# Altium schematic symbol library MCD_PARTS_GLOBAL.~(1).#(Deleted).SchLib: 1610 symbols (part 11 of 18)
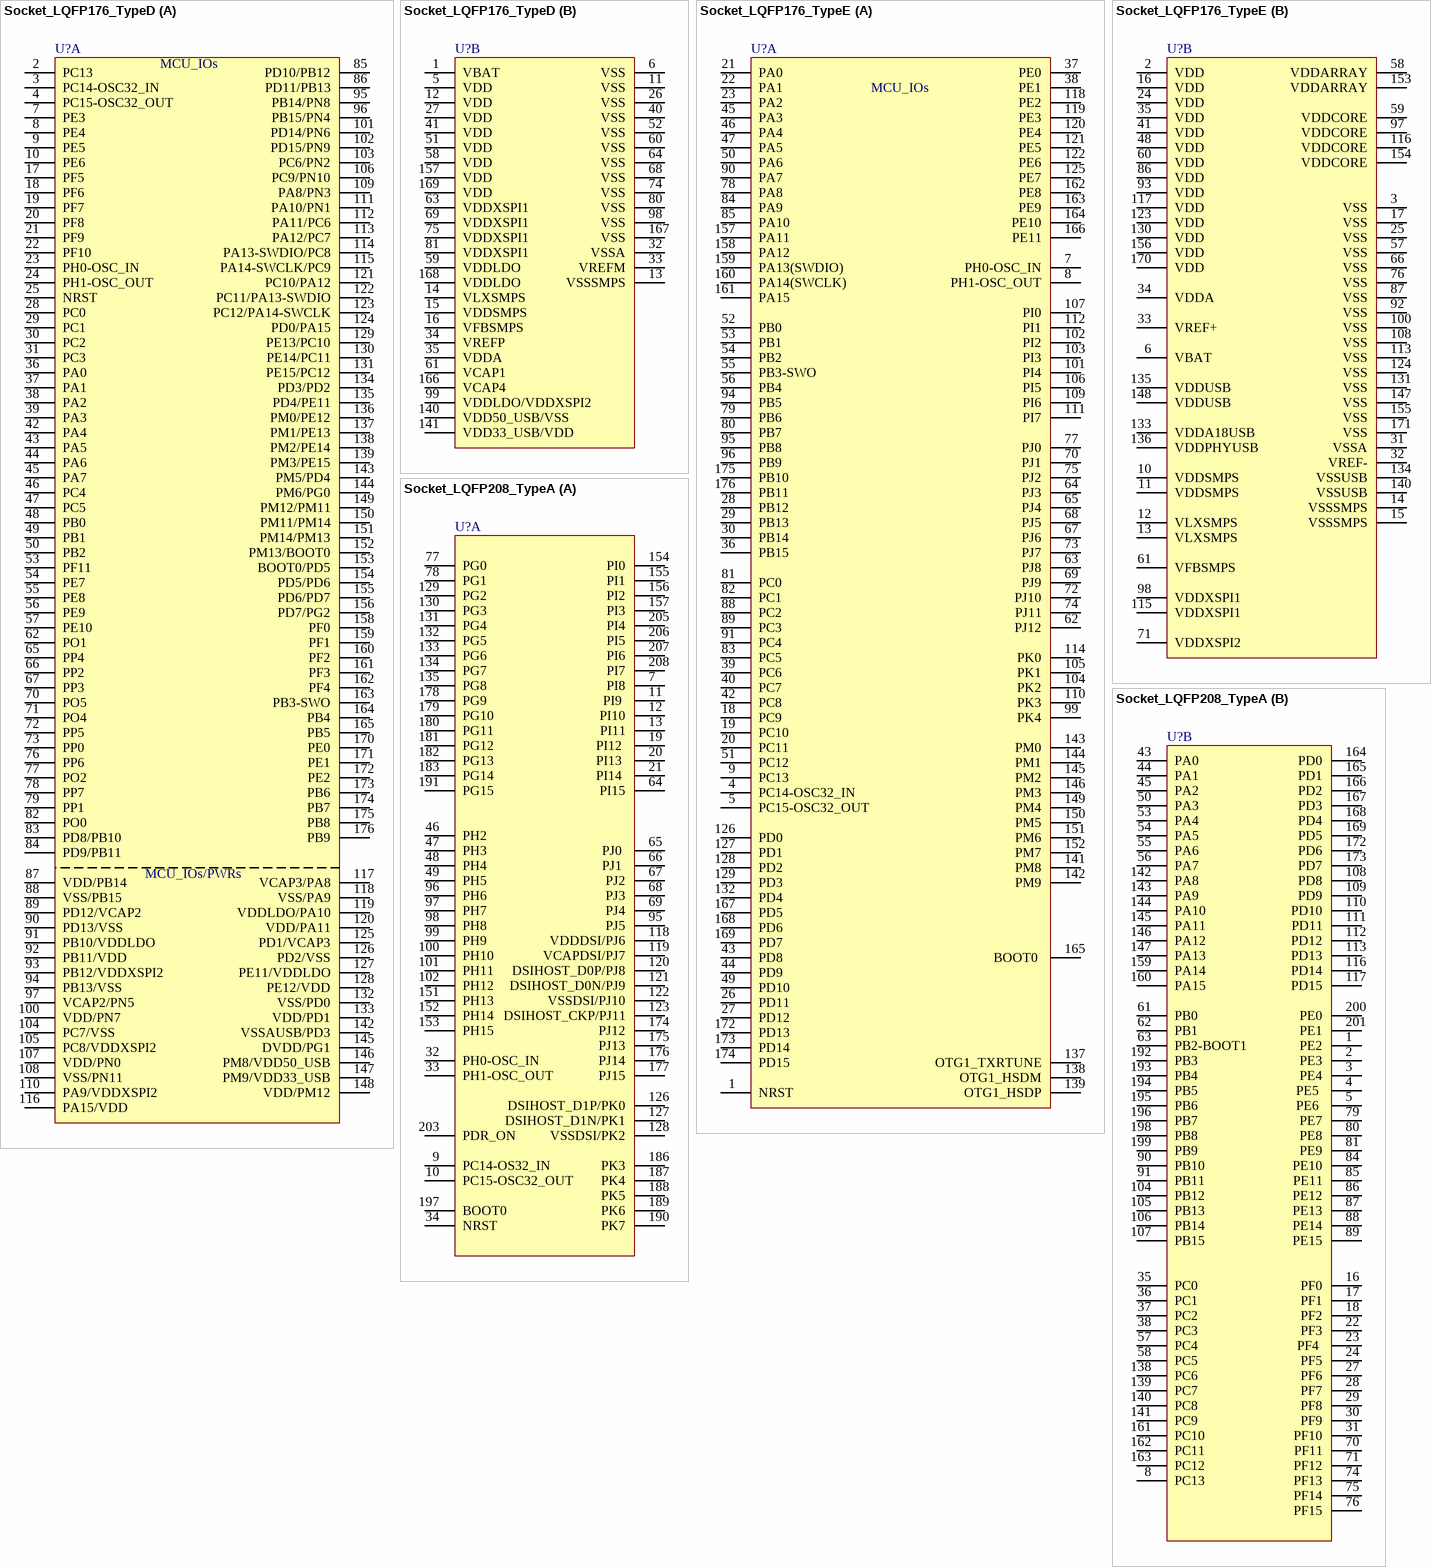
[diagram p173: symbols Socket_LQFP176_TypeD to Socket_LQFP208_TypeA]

## Socket_LQFP176_TypeD
designator U?
part A pins: 2 PC13, 3 PC14-OSC32_IN, 4 PC15-OSC32_OUT, 7 PE3, 8 PE4, 9 PE5, 10 PE6, 17 PF5, 18 PF6, 19 PF7, 20 PF8, 21 PF9, 22 PF10, 23 PH0-OSC_IN, 24 PH1-OSC_OUT, 25 NRST, 28 PC0, 29 PC1, 30 PC2, 31 PC3, 36 PA0, 37 PA1, 38 PA2, 39 PA3, 42 PA4, 43 PA5, 44 PA6, 45 PA7, 46 PC4, 47 PC5, 48 PB0, 49 PB1, 50 PB2, 53 PF11, 54 PE7, 55 PE8, 56 PE9, 57 PE10, 62 PO1, 65 PP4, 66 PP2, 67 PP3, 70 PO5, 71 PO4, 72 PP5, 73 PP0, 76 PP6, 77 PO2, 78 PP7, 79 PP1, 82 PO0, 83 PD8/PB10, 84 PD9/PB11, 85 PD10/PB12, 86 PD11/PB13, 87 VDD/PB14, 88 VSS/PB15, 89 PD12/VCAP2, 90 PD13/VSS, 91 PB10/VDDLDO, 92 PB11/VDD, 93 PB12/VDDXSPI2, 94 PB13/VSS, 95 PB14/PN8, 96 PB15/PN4, 97 VCAP2/PN5, 100 VDD/PN7, 101 PD14/PN6, 102 PD15/PN9, 103 PC6/PN2, 104 PC7/VSS, 105 PC8/VDDXSPI2, 106 PC9/PN10, 107 VDD/PN0, 108 VSS/PN11, 109 PA8/PN3, 110 PA9/VDDXSPI2, 111 PA10/PN1, 112 PA11/PC6, 113 PA12/PC7, 114 PA13-SWDIO/PC8, 115 PA14-SWCLK/PC9, 116 PA15/VDD, 117 VCAP3/PA8, 118 VSS/PA9, 119 VDDLDO/PA10, 120 VDD/PA11, 121 PC10/PA12, 122 PC11/PA13-SWDIO, 123 PC12/PA14-SWCLK, 124 PD0/PA15, 125 PD1/VCAP3, 126 PD2/VSS, 127 PE11/VDDLDO, 128 PE12/VDD, 129 PE13/PC10, 130 PE14/PC11, 131 PE15/PC12, 132 VSS/PD0, 133 VDD/PD1, 134 PD3/PD2, 135 PD4/PE11, 136 PM0/PE12, 137 PM1/PE13, 138 PM2/PE14, 139 PM3/PE15, 142 VSSAUSB/PD3, 143 PM5/PD4, 144 PM6/PG0, 145 DVDD/PG1, 146 PM8/VDD50_USB, 147 PM9/VDD33_USB, 148 VDD/PM12, 149 PM12/PM11, 150 PM11/PM14, 151 PM14/PM13, 152 PM13/BOOT0, 153 BOOT0/PD5, 154 PD5/PD6, 155 PD6/PD7, 156 PD7/PG2, 158 PF0, 159 PF1, 160 PF2, 161 PF3, 162 PF4, 163 PB3-SWO, 164 PB4, 165 PB5, 170 PE0, 171 PE1, 172 PE2, 173 PB6, 174 PB7, 175 PB8, 176 PB9
part B pins: 1 VBAT, 5 VDD, 6 VSS, 11 VSS, 12 VDD, 13 VSSSMPS, 14 VLXSMPS, 15 VDDSMPS, 16 VFBSMPS, 26 VSS, 27 VDD, 32 VSSA, 33 VREFM, 34 VREFP, 35 VDDA, 40 VSS, 41 VDD, 51 VDD, 52 VSS, 58 VDD, 59 VDDLDO, 60 VSS, 61 VCAP1, 63 VDDXSPI1, 64 VSS, 68 VSS, 69 VDDXSPI1, 74 VSS, 75 VDDXSPI1, 80 VSS, 81 VDDXSPI1, 98 VSS, 99 VDDLDO/VDDXSPI2, 140 VDD50_USB/VSS, 141 VDD33_USB/VDD, 157 VDD, 166 VCAP4, 167 VSS, 168 VDDLDO, 169 VDD

## Socket_LQFP176_TypeE
designator U?
part A pins: 1 NRST, 4 PC14-OSC32_IN, 5 PC15-OSC32_OUT, 7 PH0-OSC_IN, 8 PH1-OSC_OUT, 9 PC13, 18 PC9, 19 PC10, 20 PC11, 21 PA0, 22 PA1, 23 PA2, 26 PD11, 27 PD12, 28 PB12, 29 PB13, 30 PB14, 36 PB15, 37 PE0, 38 PE1, 39 PC6, 40 PC7, 42 PC8, 43 PD8, 44 PD9, 45 PA3, 46 PA4, 47 PA5, 49 PD10, 50 PA6, 51 PC12, 52 PB0, 53 PB1, 54 PB2, 55 PB3-SWO, 56 PB4, 62 PJ12, 63 PJ8, 64 PJ3, 65 PJ4, 67 PJ6, 68 PJ5, 69 PJ9, 70 PJ1, 72 PJ10, 73 PJ7, 74 PJ11, 75 PJ2, 77 PJ0, 78 PA8, 79 PB6, 80 PB7, 81 PC0, 82 PC1, 83 PC5, 84 PA9, 85 PA10, 88 PC2, 89 PC3, 90 PA7, 91 PC4, 94 PB5, 95 PB8, 96 PB9, 99 PK4, 101 PI4, 102 PI2, 103 PI3, 104 PK2, 105 PK1, 106 PI5, 107 PI0, 109 PI6, 110 PK3, 111 PI7, 112 PI1, 114 PK0, 118 PE2, 119 PE3, 120 PE4, 121 PE5, 122 PE6, 125 PE7, 126 PD0, 127 PD1, 128 PD2, 129 PD3, 132 PD4, 137 OTG1_TXRTUNE, 138 OTG1_HSDM, 139 OTG1_HSDP, 141 PM8, 142 PM9, 143 PM0, 144 PM1, 145 PM2, 146 PM3, 149 PM4, 150 PM5, 151 PM6, 152 PM7, 157 PA11, 158 PA12, 159 PA13(SWDIO), 160 PA14(SWCLK), 161 PA15, 162 PE8, 163 PE9, 164 PE10, 165 BOOT0 , 166 PE11, 167 PD5, 168 PD6, 169 PD7, 172 PD13, 173 PD14, 174 PD15, 175 PB10, 176 PB11
part B pins: 2 VDD, 3 VSS, 6 VBAT, 10 VDDSMPS, 11 VDDSMPS, 12 VLXSMPS, 13 VLXSMPS, 14 VSSSMPS, 15 VSSSMPS, 16 VDD, 17 VSS, 24 VDD, 25 VSS, 31 VSSA, 32 VREF-, 33 VREF+, 34 VDDA, 35 VDD, 41 VDD, 48 VDD, 57 VSS, 58 VDDARRAY, 59 VDDCORE, 60 VDD, 61 VFBSMPS, 66 VSS, 71 VDDXSPI2, 76 VSS, 86 VDD, 87 VSS, 92 VSS, 93 VDD, 97 VDDCORE, 98 VDDXSPI1, 100 VSS, 108 VSS, 113 VSS, 115 VDDXSPI1, 116 VDDCORE, 117 VDD, 123 VDD, 124 VSS, 130 VDD, 131 VSS, 133 VDDA18USB, 134 VSSUSB, 135 VDDUSB, 136 VDDPHYUSB, 140 VSSUSB, 147 VSS, 148 VDDUSB, 153 VDDARRAY, 154 VDDCORE, 155 VSS, 156 VDD, 170 VDD, 171 VSS

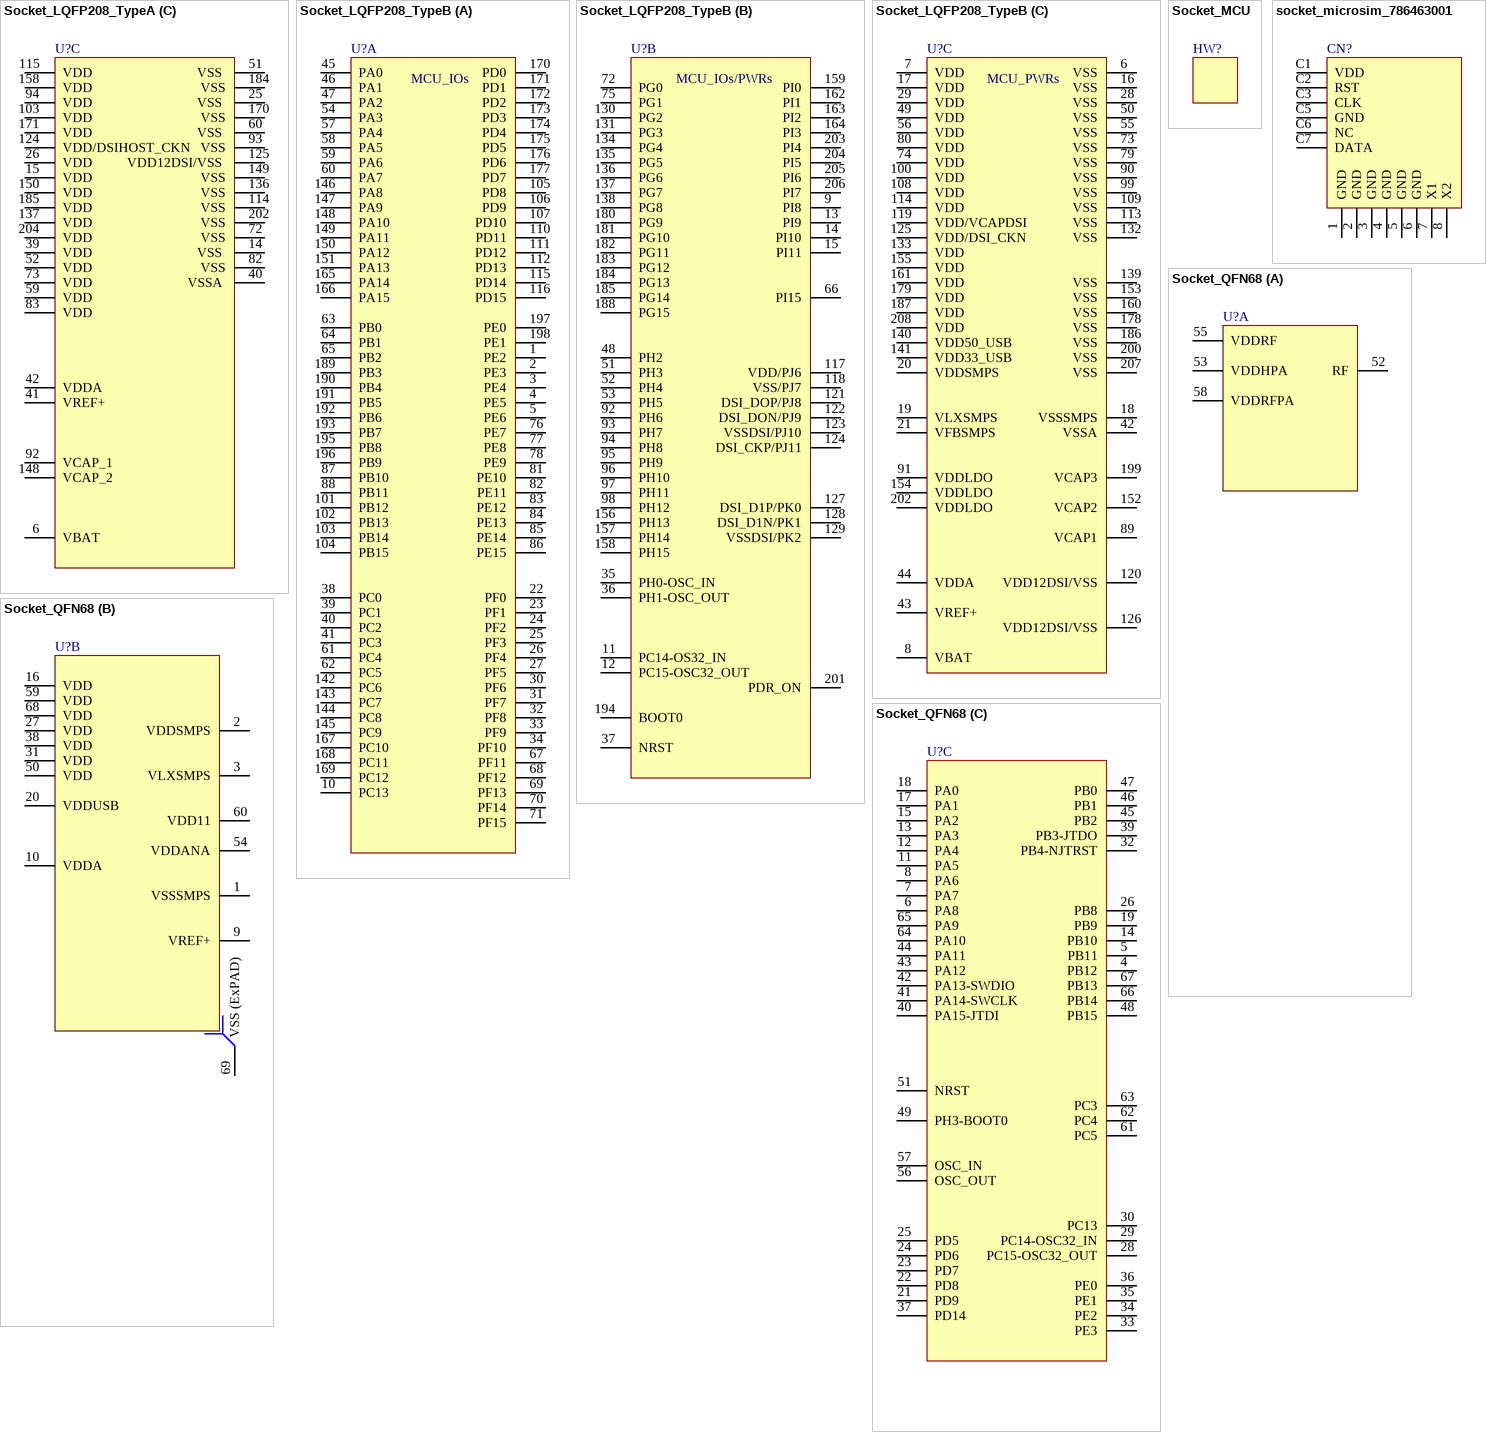
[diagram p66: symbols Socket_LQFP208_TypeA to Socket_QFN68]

## Socket_LQFP208_TypeA
designator U?
part A pins: 7 PI8, 9 PC14-OS32_IN, 10 PC15-OSC32_OUT, 11 PI9 , 12 PI10, 13 PI11, 19 PI12 , 20 PI13 , 21 PI14 , 32 PH0-OSC_IN , 33 PH1-OSC_OUT , 34 NRST , 46 PH2 , 47 PH3 , 48 PH4 , 49 PH5 , 64 PI15, 65 PJ0 , 66 PJ1 , 67 PJ2, 68 PJ3, 69 PJ4, 77 PG0, 78 PG1, 95 PJ5, 96 PH6, 97 PH7, 98 PH8, 99 PH9, 100 PH10, 101 PH11, 102 PH12, 118 VDDDSI/PJ6, 119 VCAPDSI/PJ7, 120 DSIHOST_D0P/PJ8, 121 DSIHOST_D0N/PJ9, 122 VSSDSI/PJ10, 123 DSIHOST_CKP/PJ11, 126 DSIHOST_D1P/PK0, 127 DSIHOST_D1N/PK1, 128 VSSDSI/PK2, 129 PG2, 130 PG3, 131 PG4, 132 PG5, 133 PG6, 134 PG7, 135 PG8, 151 PH13, 152 PH14, 153 PH15, 154 PI0, 155 PI1, 156 PI2, 157 PI3, 174 PJ12, 175 PJ13, 176 PJ14, 177 PJ15, 178 PG9, 179 PG10, 180 PG11, 181 PG12 , 182 PG13, 183 PG14, 186 PK3, 187 PK4, 188 PK5, 189 PK6, 190 PK7, 191 PG15, 197 BOOT0, 203 PDR_ON, 205 PI4, 206 PI5, 207 PI6, 208 PI7
part B pins: 1 PE2, 2 PE3, 3 PE4, 4 PE5 , 5 PE6 , 8 PC13 , 16 PF0, 17 PF1, 18 PF2, 22 PF3, 23 PF4 , 24 PF5, 27 PF6, 28 PF7, 29 PF8, 30 PF9, 31 PF10, 35 PC0, 36 PC1 , 37 PC2  , 38 PC3 , 43 PA0 , 44 PA1, 45 PA2 , 50 PA3 , 53 PA4 , 54 PA5 , 55 PA6, 56 PA7, 57 PC4, 58 PC5 , 61 PB0 , 62 PB1 , 63 PB2-BOOT1 , 70 PF11, 71 PF12, 74 PF13, 75 PF14, 76 PF15, 79 PE7, 80 PE8, 81 PE9, 84 PE10, 85 PE11, 86 PE12, 87 PE13, 88 PE14, 89 PE15, 90 PB10, 91 PB11, 104 PB12, 105 PB13, 106 PB14, 107 PB15, 108 PD8, 109 PD9, 110 PD10, 111 PD11, 112 PD12, 113 PD13, 116 PD14, 117 PD15, 138 PC6, 139 PC7, 140 PC8, 141 PC9, 142 PA8, 143 PA9 , 144 PA10, 145 PA11, 146 PA12, 147 PA13, 159 PA14, 160 PA15, 161 PC10, 162 PC11, 163 PC12, 164 PD0, 165 PD1, 166 PD2, 167 PD3, 168 PD4, 169 PD5, 172 PD6, 173 PD7, 192 PB3, 193 PB4, 194 PB5, 195 PB6, 196 PB7, 198 PB8, 199 PB9, 200 PE0, 201 PE1
part C pins: 6 VBAT , 14 VSS , 15 VDD, 25 VSS , 26 VDD, 39 VDD , 40 VSSA , 41 VREF+ , 42 VDDA , 51 VSS , 52 VDD, 59 VDD , 60 VSS , 72 VSS, 73 VDD, 82 VSS, 83 VDD, 92 VCAP_1, 93 VSS, 94 VDD, 103 VDD, 114 VSS, 115 VDD, 124 VDD/DSIHOST_CKN, 125 VDD12DSI/VSS , 136 VSS, 137 VDD, 148 VCAP_2 , 149 VSS, 150 VDD, 158 VDD, 170 VSS, 171 VDD, 184 VSS, 185 VDD, 202 VSS, 204 VDD

## Socket_LQFP208_TypeB
designator U?
part A pins: 1 PE2, 2 PE3, 3 PE4, 4 PE5, 5 PE6, 10 PC13, 22 PF0, 23 PF1, 24 PF2, 25 PF3, 26 PF4, 27 PF5, 30 PF6, 31 PF7, 32 PF8, 33 PF9, 34 PF10, 38 PC0, 39 PC1, 40 PC2, 41 PC3, 45 PA0, 46 PA1, 47 PA2, 54 PA3, 57 PA4, 58 PA5, 59 PA6, 60 PA7, 61 PC4, 62 PC5, 63 PB0, 64 PB1, 65 PB2, 67 PF11, 68 PF12, 69 PF13, 70 PF14, 71 PF15, 76 PE7, 77 PE8, 78 PE9, 81 PE10, 82 PE11, 83 PE12, 84 PE13, 85 PE14, 86 PE15, 87 PB10, 88 PB11, 101 PB12, 102 PB13, 103 PB14, 104 PB15, 105 PD8, 106 PD9, 107 PD10, 110 PD11, 111 PD12, 112 PD13, 115 PD14, 116 PD15, 142 PC6, 143 PC7, 144 PC8, 145 PC9, 146 PA8, 147 PA9, 148 PA10, 149 PA11, 150 PA12, 151 PA13, 165 PA14, 166 PA15, 167 PC10, 168 PC11, 169 PC12, 170 PD0, 171 PD1, 172 PD2, 173 PD3, 174 PD4, 175 PD5, 176 PD6, 177 PD7, 189 PB3, 190 PB4, 191 PB5, 192 PB6, 193 PB7, 195 PB8, 196 PB9, 197 PE0, 198 PE1
part B pins: 9 PI8, 11 PC14-OS32_IN, 12 PC15-OSC32_OUT, 13 PI9, 14 PI10, 15 PI11, 35 PH0-OSC_IN, 36 PH1-OSC_OUT, 37 NRST, 48 PH2, 51 PH3, 52 PH4, 53 PH5, 66 PI15, 72 PG0, 75 PG1, 92 PH6, 93 PH7, 94 PH8, 95 PH9, 96 PH10, 97 PH11, 98 PH12, 117 VDD/PJ6, 118 VSS/PJ7, 121 DSI_DOP/PJ8, 122 DSI_DON/PJ9, 123 VSSDSI/PJ10, 124 DSI_CKP/PJ11, 127 DSI_D1P/PK0, 128 DSI_D1N/PK1, 129 VSSDSI/PK2, 130 PG2, 131 PG3, 134 PG4, 135 PG5, 136 PG6, 137 PG7, 138 PG8, 156 PH13, 157 PH14, 158 PH15, 159 PI0, 162 PI1, 163 PI2, 164 PI3, 180 PG9, 181 PG10, 182 PG11, 183 PG12, 184 PG13, 185 PG14, 188 PG15, 194 BOOT0, 201 PDR_ON, 203 PI4, 204 PI5, 205 PI6, 206 PI7
part C pins: 6 VSS, 7 VDD, 8 VBAT, 16 VSS, 17 VDD, 18 VSSSMPS, 19 VLXSMPS, 20 VDDSMPS, 21 VFBSMPS, 28 VSS, 29 VDD, 42 VSSA, 43 VREF+, 44 VDDA, 49 VDD, 50 VSS, 55 VSS, 56 VDD, 73 VSS, 74 VDD, 79 VSS, 80 VDD, 89 VCAP1, 90 VSS, 91 VDDLDO, 99 VSS, 100 VDD, 108 VDD, 109 VSS, 113 VSS, 114 VDD, 119 VDD/VCAPDSI, 120 VDD12DSI/VSS, 125 VDD/DSI_CKN, 126 VDD12DSI/VSS, 132 VSS, 133 VDD, 139 VSS, 140 VDD50_USB, 141 VDD33_USB, 152 VCAP2, 153 VSS, 154 VDDLDO, 155 VDD, 160 VSS, 161 VDD, 178 VSS, 179 VDD, 186 VSS, 187 VDD, 199 VCAP3, 200 VSS, 202 VDDLDO, 207 VSS, 208 VDD

## Socket_MCU
designator HW?  (mechanical)
6 alternate drawings of the same symbol

## socket_microsim_786463001
designator CN?
pins: 1 GND, 2 GND, 3 GND, 4 GND, 5 GND, 6 GND, 7 X1, 8 X2, C1 VDD, C2 RST, C3 CLK, C5 GND, C6 NC, C7 DATA

## Socket_QFN68
designator U?
part A pins: 52 RF, 53 VDDHPA, 55 VDDRF, 58 VDDRFPA
part B pins: 1 VSSSMPS, 2 VDDSMPS, 3 VLXSMPS, 9 VREF+, 10 VDDA, 16 VDD, 20 VDDUSB, 27 VDD, 31 VDD, 38 VDD, 50 VDD, 54 VDDANA, 59 VDD, 60 VDD11, 68 VDD, 69 VSS (ExPAD)
part C pins: 4 PB12, 5 PB11, 6 PA8, 7 PA7, 8 PA6, 11 PA5, 12 PA4, 13 PA3, 14 PB10, 15 PA2, 17 PA1, 18 PA0, 19 PB9, 21 PD9, 22 PD8, 23 PD7, 24 PD6, 25 PD5, 26 PB8, 28 PC15-OSC32_OUT, 29 PC14-OSC32_IN, 30 PC13, 32 PB4-NJTRST, 33 PE3, 34 PE2, 35 PE1, 36 PE0, 37 PD14, 39 PB3-JTDO, 40 PA15-JTDI, 41 PA14-SWCLK, 42 PA13-SWDIO, 43 PA12, 44 PA11, 45 PB2, 46 PB1, 47 PB0, 48 PB15, 49 PH3-BOOT0, 51 NRST, 56 OSC_OUT, 57 OSC_IN, 61 PC5, 62 PC4, 63 PC3, 64 PA10, 65 PA9, 66 PB14, 67 PB13

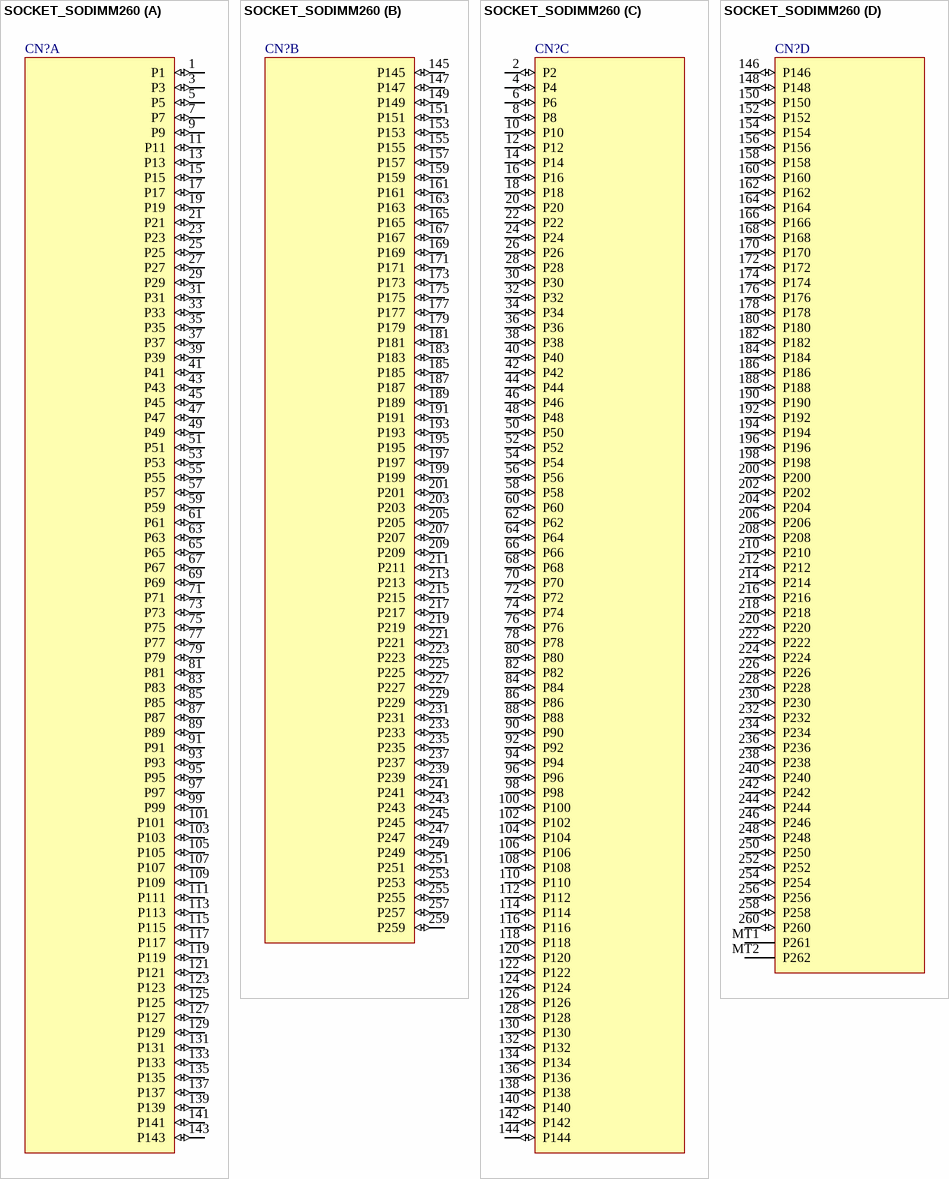
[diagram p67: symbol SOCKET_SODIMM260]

## SOCKET_SODIMM260
designator CN?
part A pins: 1 P1 (io), 3 P3 (io), 5 P5 (io), 7 P7 (io), 9 P9 (io), 11 P11 (io), 13 P13 (io), 15 P15 (io), 17 P17 (io), 19 P19 (io), 21 P21 (io), 23 P23 (io), 25 P25 (io), 27 P27 (io), 29 P29 (io), 31 P31 (io), 33 P33 (io), 35 P35 (io), 37 P37 (io), 39 P39 (io), 41 P41 (io), 43 P43 (io), 45 P45 (io), 47 P47 (io), 49 P49 (io), 51 P51 (io), 53 P53 (io), 55 P55 (io), 57 P57 (io), 59 P59 (io), 61 P61 (io), 63 P63 (io), 65 P65 (io), 67 P67 (io), 69 P69 (io), 71 P71 (io), 73 P73 (io), 75 P75 (io), 77 P77 (io), 79 P79 (io), 81 P81 (io), 83 P83 (io), 85 P85 (io), 87 P87 (io), 89 P89 (io), 91 P91 (io), 93 P93 (io), 95 P95 (io), 97 P97 (io), 99 P99 (io), 101 P101 (io), 103 P103 (io), 105 P105 (io), 107 P107 (io), 109 P109 (io), 111 P111 (io), 113 P113 (io), 115 P115 (io), 117 P117 (io), 119 P119 (io), 121 P121 (io), 123 P123 (io), 125 P125 (io), 127 P127 (io), 129 P129 (io), 131 P131 (io), 133 P133 (io), 135 P135 (io), 137 P137 (io), 139 P139 (io), 141 P141 (io), 143 P143 (io)
part B pins: 145 P145 (io), 147 P147 (io), 149 P149 (io), 151 P151 (io), 153 P153 (io), 155 P155 (io), 157 P157 (io), 159 P159 (io), 161 P161 (io), 163 P163 (io), 165 P165 (io), 167 P167 (io), 169 P169 (io), 171 P171 (io), 173 P173 (io), 175 P175 (io), 177 P177 (io), 179 P179 (io), 181 P181 (io), 183 P183 (io), 185 P185 (io), 187 P187 (io), 189 P189 (io), 191 P191 (io), 193 P193 (io), 195 P195 (io), 197 P197 (io), 199 P199 (io), 201 P201 (io), 203 P203 (io), 205 P205 (io), 207 P207 (io), 209 P209 (io), 211 P211 (io), 213 P213 (io), 215 P215 (io), 217 P217 (io), 219 P219 (io), 221 P221 (io), 223 P223 (io), 225 P225 (io), 227 P227 (io), 229 P229 (io), 231 P231 (io), 233 P233 (io), 235 P235 (io), 237 P237 (io), 239 P239 (io), 241 P241 (io), 243 P243 (io), 245 P245 (io), 247 P247 (io), 249 P249 (io), 251 P251 (io), 253 P253 (io), 255 P255 (io), 257 P257 (io), 259 P259 (io)
part C pins: 2 P2 (io), 4 P4 (io), 6 P6 (io), 8 P8 (io), 10 P10 (io), 12 P12 (io), 14 P14 (io), 16 P16 (io), 18 P18 (io), 20 P20 (io), 22 P22 (io), 24 P24 (io), 26 P26 (io), 28 P28 (io), 30 P30 (io), 32 P32 (io), 34 P34 (io), 36 P36 (io), 38 P38 (io), 40 P40 (io), 42 P42 (io), 44 P44 (io), 46 P46 (io), 48 P48 (io), 50 P50 (io), 52 P52 (io), 54 P54 (io), 56 P56 (io), 58 P58 (io), 60 P60 (io), 62 P62 (io), 64 P64 (io), 66 P66 (io), 68 P68 (io), 70 P70 (io), 72 P72 (io), 74 P74 (io), 76 P76 (io), 78 P78 (io), 80 P80 (io), 82 P82 (io), 84 P84 (io), 86 P86 (io), 88 P88 (io), 90 P90 (io), 92 P92 (io), 94 P94 (io), 96 P96 (io), 98 P98 (io), 100 P100 (io), 102 P102 (io), 104 P104 (io), 106 P106 (io), 108 P108 (io), 110 P110 (io), 112 P112 (io), 114 P114 (io), 116 P116 (io), 118 P118 (io), 120 P120 (io), 122 P122 (io), 124 P124 (io), 126 P126 (io), 128 P128 (io), 130 P130 (io), 132 P132 (io), 134 P134 (io), 136 P136 (io), 138 P138 (io), 140 P140 (io), 142 P142 (io), 144 P144 (io)
part D pins: 146 P146 (io), 148 P148 (io), 150 P150 (io), 152 P152 (io), 154 P154 (io), 156 P156 (io), 158 P158 (io), 160 P160 (io), 162 P162 (io), 164 P164 (io), 166 P166 (io), 168 P168 (io), 170 P170 (io), 172 P172 (io), 174 P174 (io), 176 P176 (io), 178 P178 (io), 180 P180 (io), 182 P182 (io), 184 P184 (io), 186 P186 (io), 188 P188 (io), 190 P190 (io), 192 P192 (io), 194 P194 (io), 196 P196 (io), 198 P198 (io), 200 P200 (io), 202 P202 (io), 204 P204 (io), 206 P206 (io), 208 P208 (io), 210 P210 (io), 212 P212 (io), 214 P214 (io), 216 P216 (io), 218 P218 (io), 220 P220 (io), 222 P222 (io), 224 P224 (io), 226 P226 (io), 228 P228 (io), 230 P230 (io), 232 P232 (io), 234 P234 (io), 236 P236 (io), 238 P238 (io), 240 P240 (io), 242 P242 (io), 244 P244 (io), 246 P246 (io), 248 P248 (io), 250 P250 (io), 252 P252 (io), 254 P254 (io), 256 P256 (io), 258 P258 (io), 260 P260 (io), MT1 P261, MT2 P262

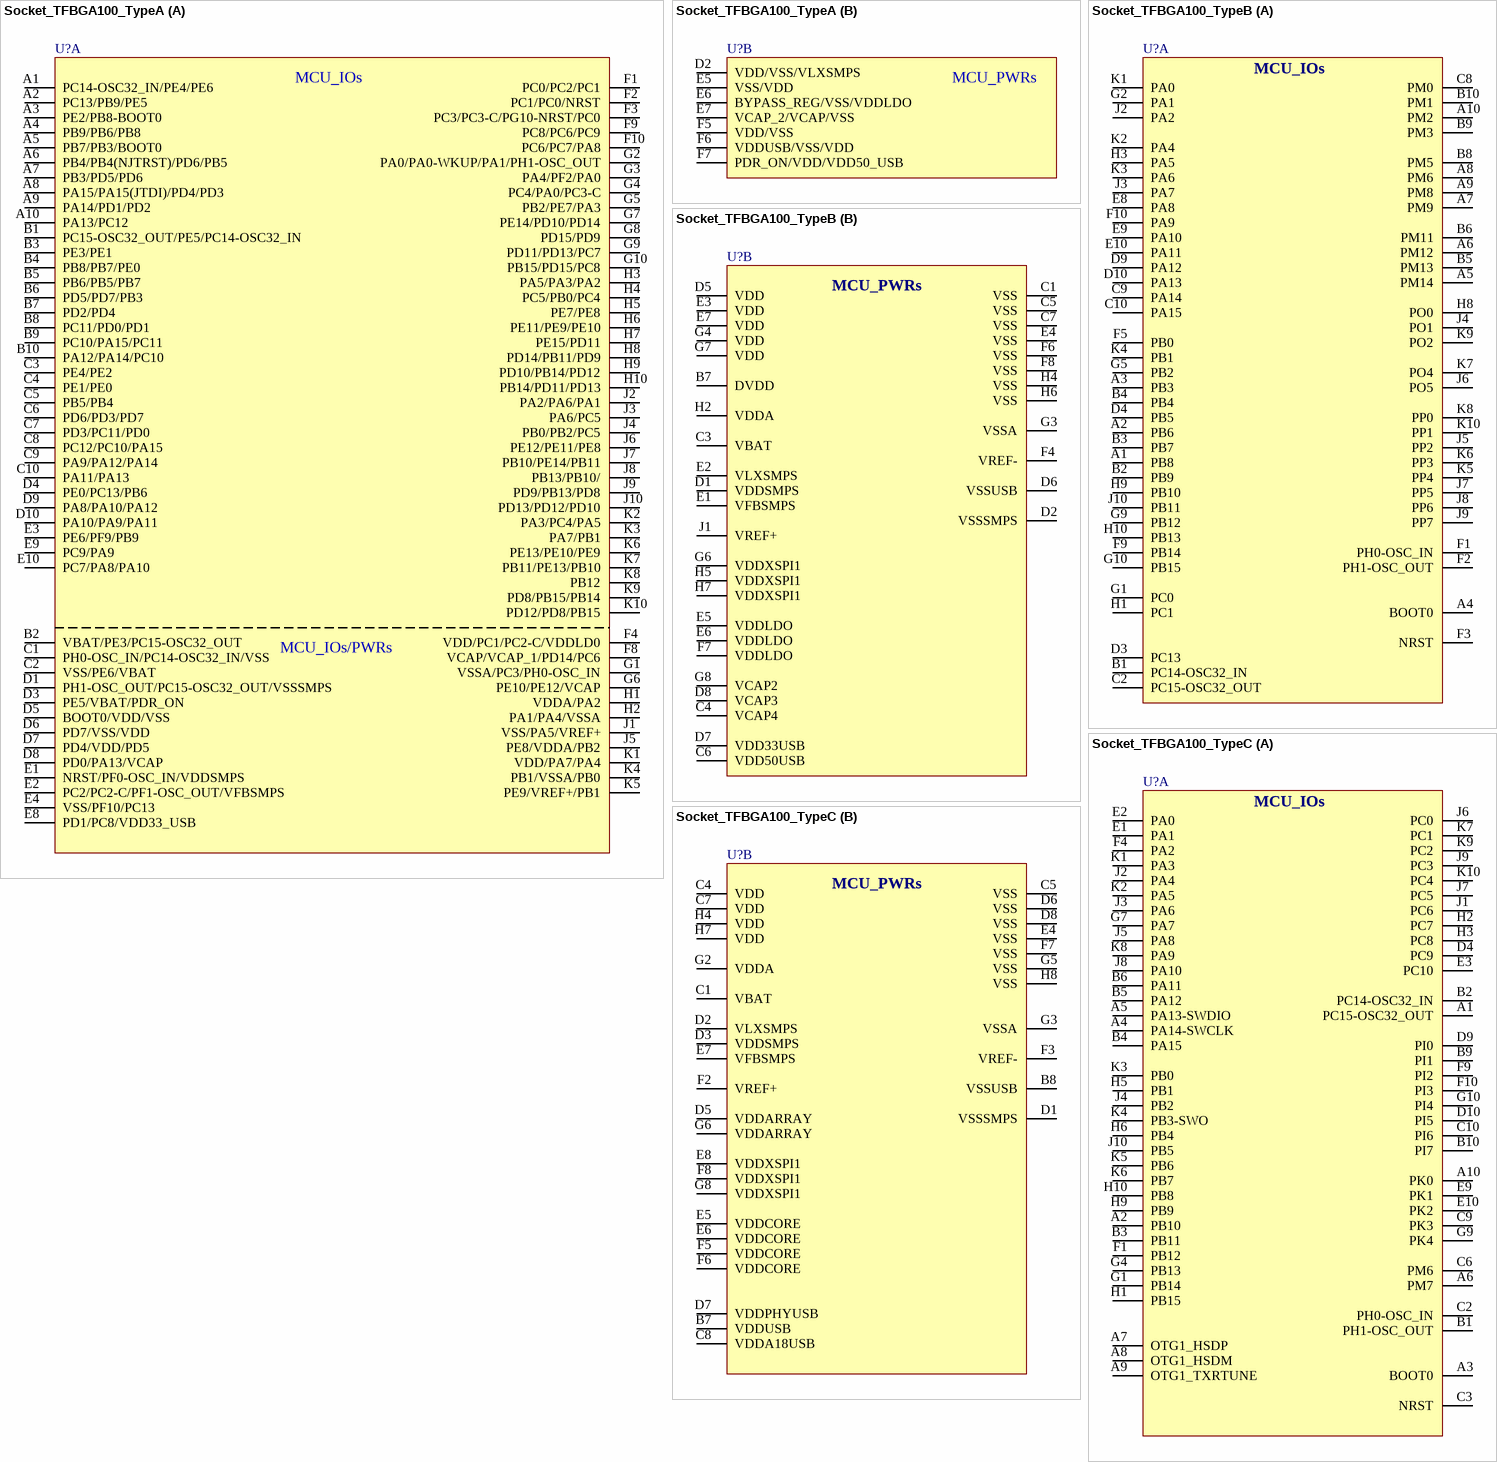
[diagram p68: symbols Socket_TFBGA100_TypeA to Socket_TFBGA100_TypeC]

## Socket_TFBGA100_TypeA
designator U?
part A pins: A1 PC14-OSC32_IN/PE4/PE6, A2 PC13/PB9/PE5, A3 PE2/PB8-BOOT0, A4 PB9/PB6/PB8, A5 PB7/PB3/BOOT0, A6 PB4/PB4(NJTRST)/PD6/PB5, A7 PB3/PD5/PD6, A8 PA15/PA15(JTDI)/PD4/PD3, A9 PA14/PD1/PD2, A10 PA13/PC12, B1 PC15-OSC32_OUT/PE5/PC14-OSC32_IN, B2 VBAT/PE3/PC15-OSC32_OUT, B3 PE3/PE1, B4 PB8/PB7/PE0, B5 PB6/PB5/PB7, B6 PD5/PD7/PB3, B7 PD2/PD4, B8 PC11/PD0/PD1, B9 PC10/PA15/PC11, B10 PA12/PA14/PC10, C1 PH0-OSC_IN/PC14-OSC32_IN/VSS, C2 VSS/PE6/VBAT, C3 PE4/PE2, C4 PE1/PE0, C5 PB5/PB4, C6 PD6/PD3/PD7, C7 PD3/PC11/PD0, C8 PC12/PC10/PA15, C9 PA9/PA12/PA14, C10 PA11/PA13, D1 PH1-OSC_OUT/PC15-OSC32_OUT/VSSSMPS, D3 PE5/VBAT/PDR_ON, D4 PE0/PC13/PB6, D5 BOOT0/VDD/VSS, D6 PD7/VSS/VDD, D7 PD4/VDD/PD5, D8 PD0/PA13/VCAP, D9 PA8/PA10/PA12, D10 PA10/PA9/PA11, E1 NRST/PF0-OSC_IN/VDDSMPS, E2 PC2/PC2-C/PF1-OSC_OUT/VFBSMPS, E3 PE6/PF9/PB9, E4 VSS/PF10/PC13, E8 PD1/PC8/VDD33_USB, E9 PC9/PA9, E10 PC7/PA8/PA10, F1 PC0/PC2/PC1, F2 PC1/PC0/NRST, F3 PC3/PC3-C/PG10-NRST/PC0, F4 VDD/PC1/PC2-C/VDDLD0, F8 VCAP/VCAP_1/PD14/PC6, F9 PC8/PC6/PC9, F10 PC6/PC7/PA8, G1 VSSA/PC3/PH0-OSC_IN, G2 PA0/PA0-WKUP/PA1/PH1-OSC_OUT, G3 PA4/PF2/PA0, G4 PC4/PA0/PC3-C, G5 PB2/PE7/PA3, G6 PE10/PE12/VCAP, G7 PE14/PD10/PD14, G8 PD15/PD9, G9 PD11/PD13/PC7, G10 PB15/PD15/PC8, H1 VDDA/PA2, H2 PA1/PA4/VSSA, H3 PA5/PA3/PA2, H4 PC5/PB0/PC4, H5 PE7/PE8, H6 PE11/PE9/PE10, H7 PE15/PD11, H8 PD14/PB11/PD9, H9 PD10/PB14/PD12, H10 PB14/PD11/PD13, J1 VSS/PA5/VREF+, J2 PA2/PA6/PA1, J3 PA6/PC5, J4 PB0/PB2/PC5, J5 PE8/VDDA/PB2, J6 PE12/PE11/PE8, J7 PB10/PE14/PB11, J8 PB13/PB10/, J9 PD9/PB13/PD8, J10 PD13/PD12/PD10, K1 VDD/PA7/PA4, K2 PA3/PC4/PA5, K3 PA7/PB1, K4 PB1/VSSA/PB0, K5 PE9/VREF+/PB1, K6 PE13/PE10/PE9, K7 PB11/PE13/PB10, K8 PB12, K9 PD8/PB15/PB14, K10 PD12/PD8/PB15
part B pins: D2 VDD/VSS/VLXSMPS, E5 VSS/VDD, E6 BYPASS_REG/VSS/VDDLDO, E7 VCAP_2/VCAP/VSS, F5 VDD/VSS, F6 VDDUSB/VSS/VDD, F7 PDR_ON/VDD/VDD50_USB

## Socket_TFBGA100_TypeB
designator U?
part A pins: A1 PB8, A2 PB6, A3 PB3, A4 BOOT0, A5 PM14, A6 PM12, A7 PM9, A8 PM6, A9 PM8, A10 PM2, B1 PC14-OSC32_IN, B2 PB9, B3 PB7, B4 PB4, B5 PM13, B6 PM11, B8 PM5, B9 PM3, B10 PM1, C2 PC15-OSC32_OUT, C8 PM0, C9 PA14, C10 PA15, D3 PC13, D4 PB5, D9 PA12, D10 PA13, E8 PA8, E9 PA10, E10 PA11, F1 PH0-OSC_IN, F2 PH1-OSC_OUT, F3 NRST, F5 PB0, F9 PB14, F10 PA9, G1 PC0, G2 PA1, G5 PB2, G9 PB12, G10 PB15, H1 PC1, H3 PA5, H8 PO0, H9 PB10, H10 PB13, J2 PA2, J3 PA7, J4 PO1, J5 PP2, J6 PO5, J7 PP5, J8 PP6, J9 PP7, J10 PB11, K1 PA0, K2 PA4, K3 PA6, K4 PB1, K5 PP4, K6 PP3, K7 PO4, K8 PP0, K9 PO2, K10 PP1
part B pins: B7 DVDD, C1 VSS, C3 VBAT, C4 VCAP4, C5 VSS, C6 VDD50USB, C7 VSS, D1 VDDSMPS, D2 VSSSMPS, D5 VDD, D6 VSSUSB, D7 VDD33USB, D8 VCAP3, E1 VFBSMPS, E2 VLXSMPS, E3 VDD, E4 VSS, E5 VDDLDO, E6 VDDLDO, E7 VDD, F4 VREF-, F6 VSS, F7 VDDLDO, F8 VSS, G3 VSSA, G4 VDD, G6 VDDXSPI1, G7 VDD, G8 VCAP2, H2 VDDA, H4 VSS, H5 VDDXSPI1, H6 VSS, H7 VDDXSPI1, J1 VREF+

## Socket_TFBGA100_TypeC
designator U?
part A pins: A1 PC15-OSC32_OUT, A2 PB10, A3 BOOT0, A4 PA14-SWCLK, A5 PA13-SWDIO, A6 PM7, A7 OTG1_HSDP, A8 OTG1_HSDM, A9 OTG1_TXRTUNE, A10 PK0, B1 PH1-OSC_OUT, B2 PC14-OSC32_IN, B3 PB11, B4 PA15, B5 PA12, B6 PA11, B9 PI1, B10 PI7, C2 PH0-OSC_IN, C3 NRST, C6 PM6, C9 PK3, C10 PI6, D4 PC9, D9 PI0, D10 PI5, E1 PA1, E2 PA0, E3 PC10, E9 PK1, E10 PK2, F1 PB12, F4 PA2, F9 PI2, F10 PI3, G1 PB14, G4 PB13, G7 PA7, G9 PK4, G10 PI4, H1 PB15, H2 PC7, H3 PC8, H5 PB1, H6 PB4, H9 PB9, H10 PB8, J1 PC6, J2 PA4, J3 PA6, J4 PB2, J5 PA8, J6 PC0, J7 PC5, J8 PA10, J9 PC3, J10 PB5, K1 PA3, K2 PA5, K3 PB0, K4 PB3-SWO, K5 PB6, K6 PB7, K7 PC1, K8 PA9, K9 PC2, K10 PC4
part B pins: B7 VDDUSB, B8 VSSUSB, C1 VBAT, C4 VDD, C5 VSS, C7 VDD, C8 VDDA18USB, D1 VSSSMPS, D2 VLXSMPS, D3 VDDSMPS, D5 VDDARRAY, D6 VSS, D7 VDDPHYUSB, D8 VSS, E4 VSS, E5 VDDCORE, E6 VDDCORE, E7 VFBSMPS, E8 VDDXSPI1, F2 VREF+, F3 VREF-, F5 VDDCORE, F6 VDDCORE, F7 VSS, F8 VDDXSPI1, G2 VDDA, G3 VSSA, G5 VSS, G6 VDDARRAY, G8 VDDXSPI1, H4 VDD, H7 VDD, H8 VSS

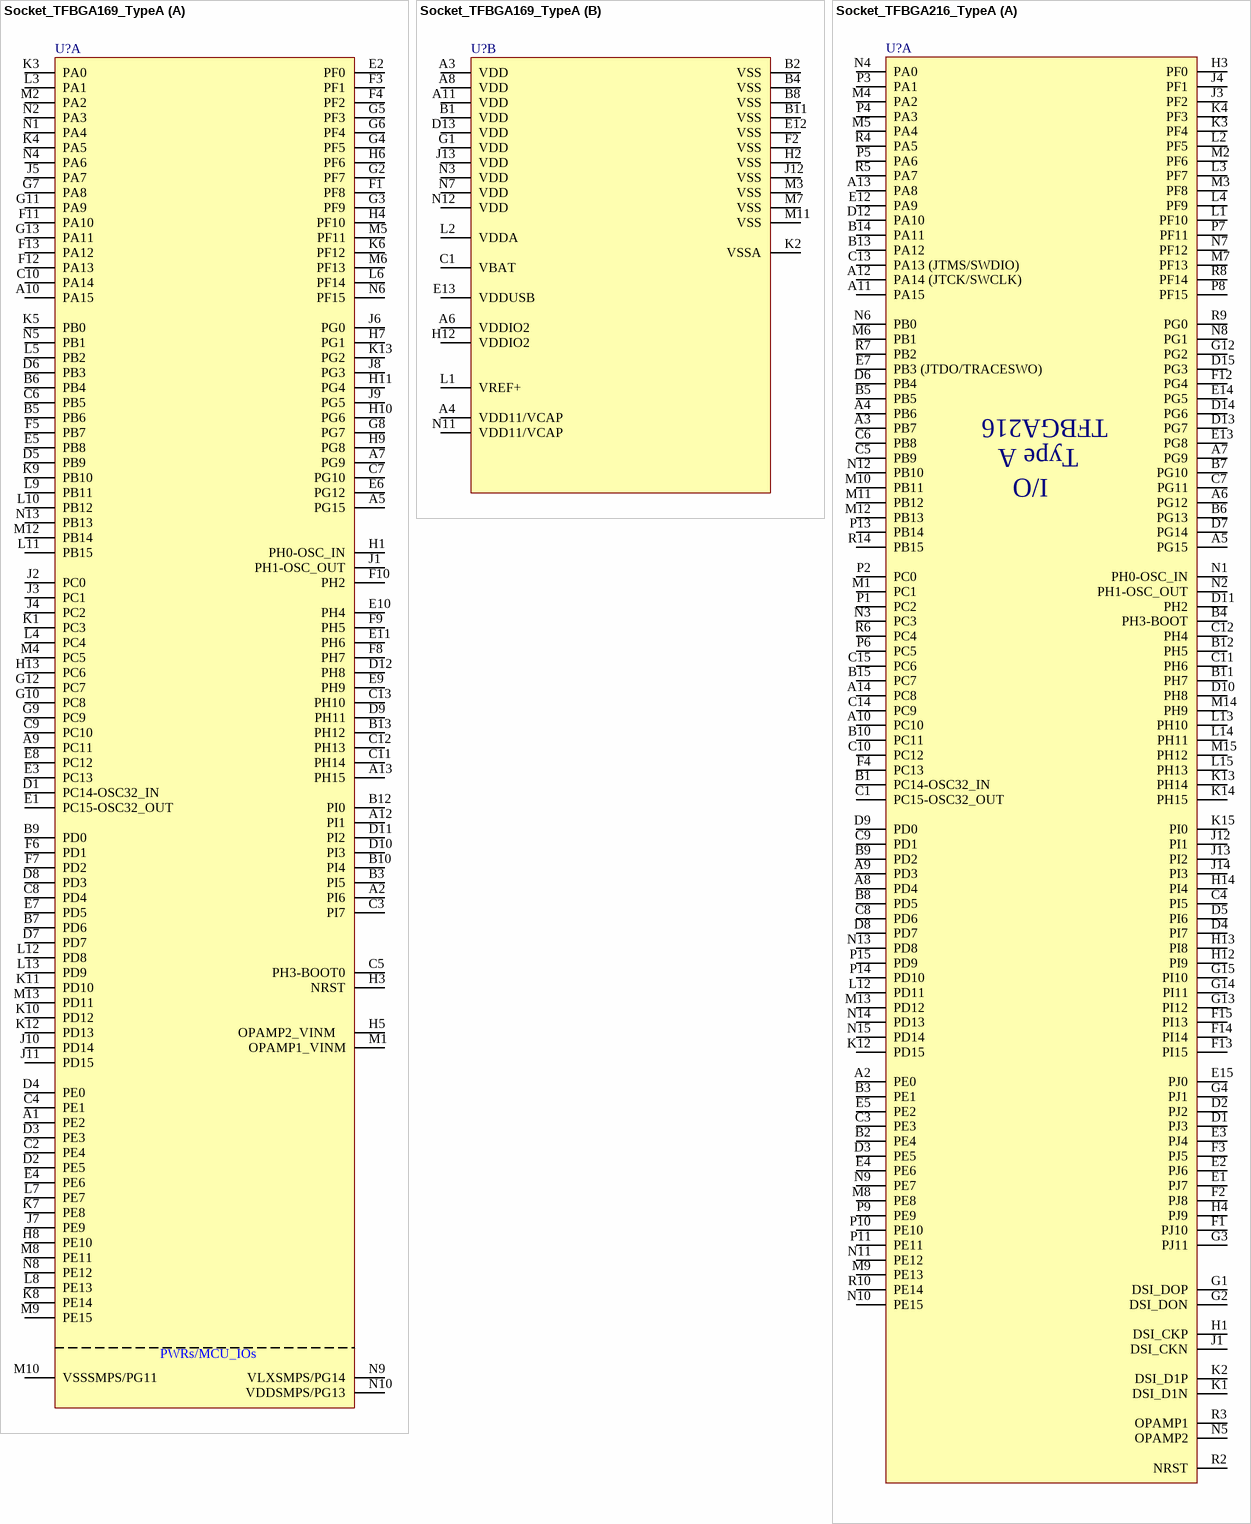
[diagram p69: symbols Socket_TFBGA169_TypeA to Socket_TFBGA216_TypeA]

## Socket_TFBGA169_TypeA
designator U?
part A pins: A1 PE2, A2 PI6, A5 PG15, A7 PG9, A9 PC11, A10 PA15, A12 PI1, A13 PH15, B3 PI5, B5 PB6, B6 PB4, B7 PD6, B9 PD0, B10 PI4, B12 PI0, B13 PH12, C2 PE4, C3 PI7, C4 PE1, C5 PH3-BOOT0, C6 PB5, C7 PG10, C8 PD4, C9 PC10, C10 PA14, C11 PH14, C12 PH13, C13 PH10, D1 PC14-OSC32_IN, D2 PE5, D3 PE3, D4 PE0, D5 PB9, D6 PB3, D7 PD7, D8 PD3, D9 PH11, D10 PI3, D11 PI2, D12 PH8, E1 PC15-OSC32_OUT, E2 PF0, E3 PC13, E4 PE6, E5 PB8, E6 PG12, E7 PD5, E8 PC12, E9 PH9, E10 PH4, E11 PH6, F1 PF8, F3 PF1, F4 PF2, F5 PB7, F6 PD1, F7 PD2, F8 PH7, F9 PH5, F10 PH2, F11 PA10, F12 PA13, F13 PA12, G2 PF7, G3 PF9, G4 PF5, G5 PF3, G6 PF4, G7 PA8, G8 PG7, G9 PC9, G10 PC8, G11 PA9, G12 PC7, G13 PA11, H1 PH0-OSC_IN, H3 NRST, H4 PF10, H5 OPAMP2_VINM   , H6 PF6, H7 PG1, H8 PE10, H9 PG8, H10 PG6, H11 PG4, H13 PC6, J1 PH1-OSC_OUT, J2 PC0, J3 PC1, J4 PC2, J5 PA7, J6 PG0, J7 PE9, J8 PG3, J9 PG5, J10 PD14, J11 PD15, K1 PC3, K3 PA0, K4 PA5, K5 PB0, K6 PF12, K7 PE8, K8 PE14, K9 PB10, K10 PD12, K11 PD10, K12 PD13, K13 PG2, L3 PA1, L4 PC4, L5 PB2, L6 PF14, L7 PE7, L8 PE13, L9 PB11, L10 PB12, L11 PB15, L12 PD8, L13 PD9, M1 OPAMP1_VINM, M2 PA2, M4 PC5, M5 PF11, M6 PF13, M8 PE11, M9 PE15, M10 VSSSMPS/PG11, M12 PB14, M13 PD11, N1 PA4, N2 PA3, N4 PA6, N5 PB1, N6 PF15, N8 PE12, N9 VLXSMPS/PG14, N10 VDDSMPS/PG13, N13 PB13
part B pins: A3 VDD, A4 VDD11/VCAP, A6 VDDIO2, A8 VDD, A11 VDD, B1 VDD, B2 VSS, B4 VSS, B8 VSS, B11 VSS, C1 VBAT, D13 VDD, E12 VSS, E13 VDDUSB, F2 VSS, G1 VDD, H2 VSS, H12 VDDIO2, J12 VSS, J13 VDD, K2 VSSA, L1 VREF+, L2 VDDA, M3 VSS, M7 VSS, M11 VSS, N3 VDD, N7 VDD, N11 VDD11/VCAP, N12 VDD

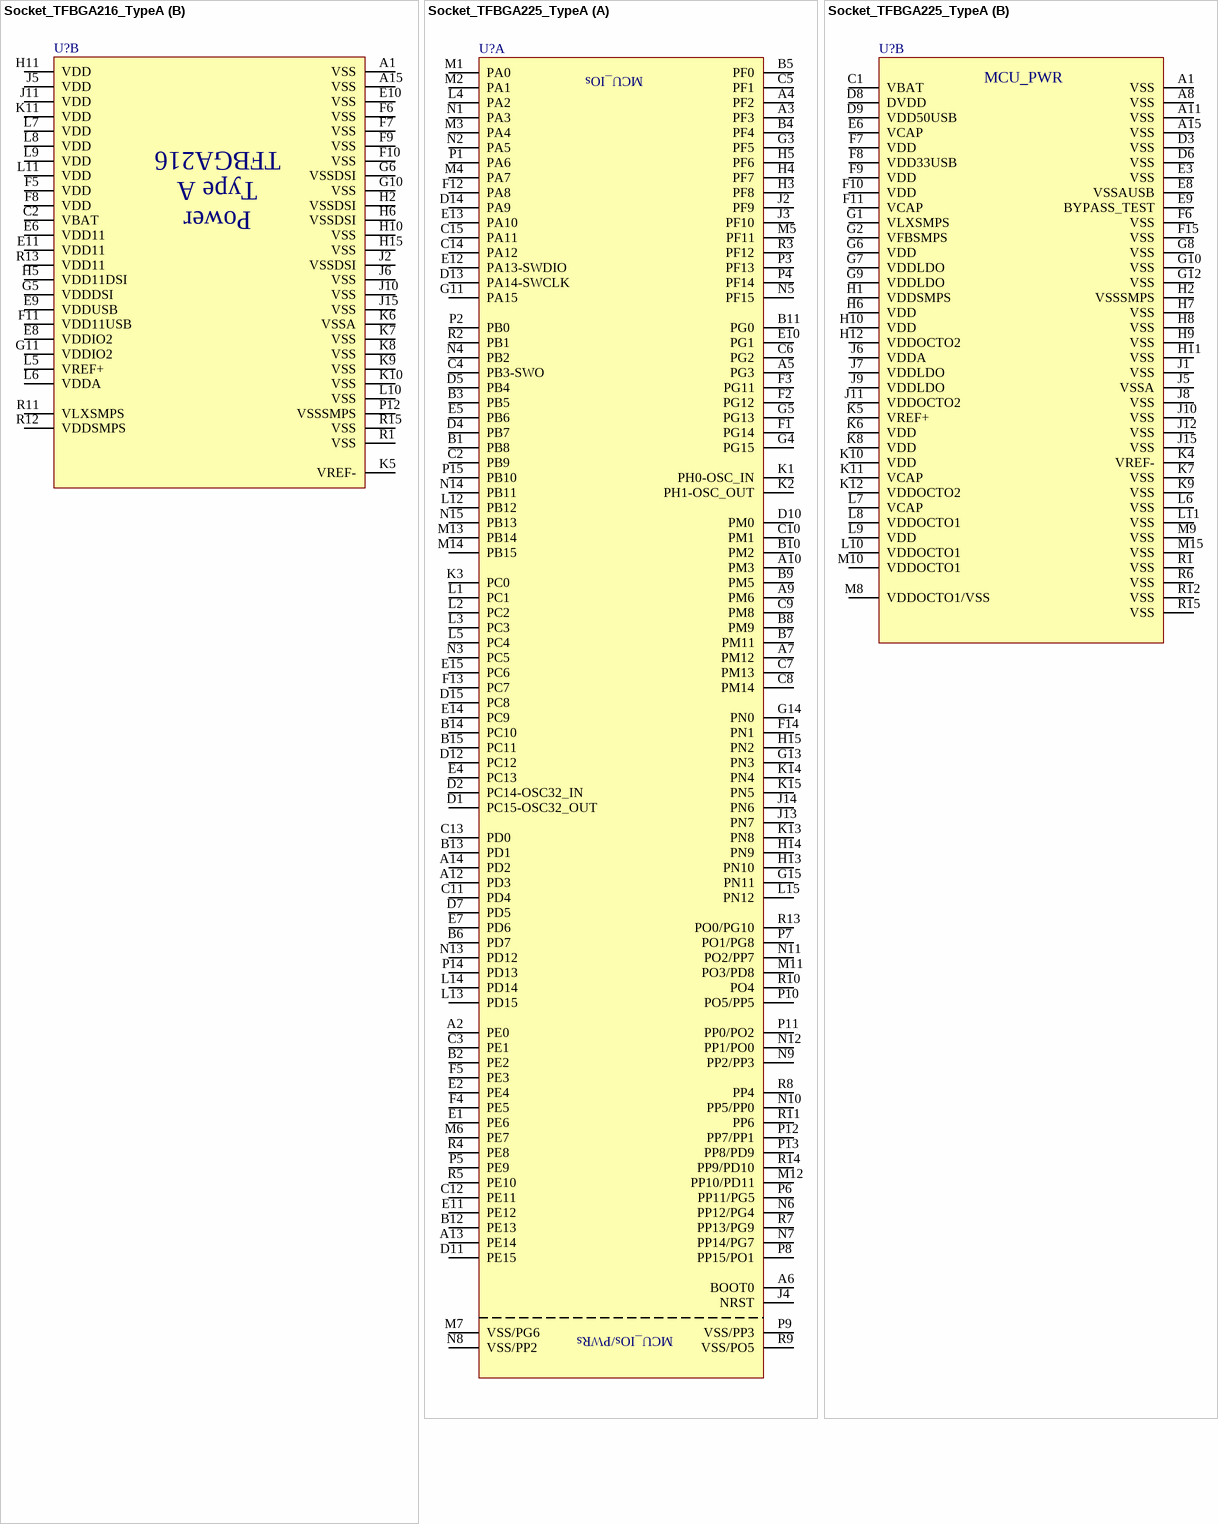
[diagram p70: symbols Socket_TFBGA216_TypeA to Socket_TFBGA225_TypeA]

## Socket_TFBGA216_TypeA
designator U?
part A pins: A2 PE0, A3 PB7, A4 PB6, A5 PG15, A6 PG12, A7 PG9, A8 PD4, A9 PD3, A10 PC10, A11 PA15, A12 PA14 (JTCK/SWCLK), A13 PA8, A14 PC8, B1 PC14-OSC32_IN, B2 PE4, B3 PE1, B4 PH3-BOOT, B5 PB5, B6 PG13, B7 PG10, B8 PD5, B9 PD2, B10 PC11, B11 PH7, B12 PH5, B13 PA12, B14 PA11, B15 PC7, C1 PC15-OSC32_OUT, C3 PE3, C4 PI5, C5 PB9, C6 PB8, C7 PG11, C8 PD6, C9 PD1, C10 PC12, C11 PH6, C12 PH4, C13 PA13 (JTMS/SWDIO), C14 PC9, C15 PC6, D1 PJ3, D2 PJ2, D3 PE5, D4 PI7, D5 PI6, D6 PB4, D7 PG14, D8 PD7, D9 PD0, D10 PH8, D11 PH2, D12 PA10, D13 PG7, D14 PG6, D15 PG3, E1 PJ7, E2 PJ6, E3 PJ4, E4 PE6, E5 PE2, E7 PB3 (JTDO/TRACESWO), E12 PA9, E13 PG8, E14 PG5, E15 PJ0, F1 PJ10, F2 PJ8, F3 PJ5, F4 PC13, F12 PG4, F13 PI15, F14 PI14, F15 PI13, G1 DSI_DOP, G2 DSI_DON, G3 PJ11, G4 PJ1, G12 PG2, G13 PI12, G14 PI11, G15 PI10, H1 DSI_CKP, H3 PF0, H4 PJ9, H12 PI9, H13 PI8, H14 PI4, J1 DSI_CKN, J3 PF2, J4 PF1, J12 PI1, J13 PI2, J14 PI3, K1 DSI_D1N, K2 DSI_D1P, K3 PF4, K4 PF3, K12 PD15, K13 PH14, K14 PH15, K15 PI0, L1 PF10, L2 PF5, L3 PF7, L4 PF9, L12 PD11, L13 PH10, L14 PH11, L15 PH13, M1 PC1, M2 PF6, M3 PF8, M4 PA2, M5 PA4, M6 PB1, M7 PF13, M8 PE8, M9 PE13, M10 PB11, M11 PB12, M12 PB13, M13 PD12, M14 PH9, M15 PH12, N1 PH0-OSC_IN, N2 PH1-OSC_OUT, N3 PC3, N4 PA0, N5 OPAMP2, N6 PB0, N7 PF12, N8 PG1, N9 PE7, N10 PE15, N11 PE12, N12 PB10, N13 PD8, N14 PD13, N15 PD14, P1 PC2, P2 PC0, P3 PA1, P4 PA3, P5 PA6, P6 PC5, P7 PF11, P8 PF15, P9 PE9, P10 PE10, P11 PE11, P13 PB14, P14 PD10, P15 PD9, R2 NRST, R3 OPAMP1, R4 PA5, R5 PA7, R6 PC4, R7 PB2, R8 PF14, R9 PG0, R10 PE14, R14 PB15
part B pins: A1 VSS, A15 VSS, C2 VBAT, E6 VDD11, E8 VDDIO2, E9 VDDUSB, E10 VSS, E11 VDD11, F5 VDD, F6 VSS, F7 VSS, F8 VDD, F9 VSS, F10 VSS, F11 VDD11USB, G5 VDDDSI, G6 VSSDSI, G10 VSS, G11 VDDIO2, H2 VSSDSI, H5 VDD11DSI, H6 VSSDSI, H10 VSS, H11 VDD, H15 VSS, J2 VSSDSI, J5 VDD, J6 VSS, J10 VSS, J11 VDD, J15 VSS, K5 VREF-, K6 VSSA, K7 VSS, K8 VSS, K9 VSS, K10 VSS, K11 VDD, L5 VREF+, L6 VDDA, L7 VDD, L8 VDD, L9 VDD, L10 VSS, L11 VDD, P12 VSSSMPS, R1 VSS, R11 VLXSMPS, R12 VDDSMPS, R13 VDD11, R15 VSS

## Socket_TFBGA225_TypeA
designator U?
part A pins: A2 PE0, A3 PF3, A4 PF2, A5 PG3, A6 BOOT0, A7 PM12, A9 PM6, A10 PM3, A12 PD3, A13 PE14, A14 PD2, B1 PB8, B2 PE2, B3 PB5, B4 PF4, B5 PF0, B6 PD7, B7 PM11, B8 PM9, B9 PM5, B10 PM2, B11 PG0, B12 PE13, B13 PD1, B14 PC10, B15 PC11, C2 PB9, C3 PE1, C4 PB3-SWO, C5 PF1, C6 PG2, C7 PM13, C8 PM14, C9 PM8, C10 PM1, C11 PD4, C12 PE11, C13 PD0, C14 PA12, C15 PA11, D1 PC15-OSC32_OUT, D2 PC14-OSC32_IN, D4 PB7, D5 PB4, D7 PD5, D10 PM0, D11 PE15, D12 PC12, D13 PA14-SWCLK, D14 PA9, D15 PC8, E1 PE6, E2 PE4, E4 PC13, E5 PB6, E7 PD6, E10 PG1, E11 PE12, E12 PA13-SWDIO, E13 PA10, E14 PC9, E15 PC6, F1 PG14, F2 PG12, F3 PG11, F4 PE5, F5 PE3, F12 PA8, F13 PC7, F14 PN1, G3 PF5, G4 PG15, G5 PG13, G11 PA15, G13 PN3, G14 PN0, G15 PN11, H3 PF8, H4 PF7, H5 PF6, H13 PN10, H14 PN9, H15 PN2, J2 PF9, J3 PF10, J4 NRST, J13 PN7, J14 PN6, K1 PH0-OSC_IN, K2 PH1-OSC_OUT, K3 PC0, K13 PN8, K14 PN4, K15 PN5, L1 PC1, L2 PC2, L3 PC3, L4 PA2, L5 PC4, L12 PB12, L13 PD15, L14 PD14, L15 PN12, M1 PA0, M2 PA1, M3 PA4, M4 PA7, M5 PF11, M6 PE7, M7 VSS/PG6, M11 PO3/PD8, M12 PP10/PD11, M13 PB14, M14 PB15, N1 PA3, N2 PA5, N3 PC5, N4 PB2, N5 PF15, N6 PP12/PG4, N7 PP14/PG7, N8 VSS/PP2, N9 PP2/PP3, N10 PP5/PP0, N11 PO2/PP7, N12 PP1/PO0, N13 PD12, N14 PB11, N15 PB13, P1 PA6, P2 PB0, P3 PF13, P4 PF14, P5 PE9, P6 PP11/PG5, P7 PO1/PG8, P8 PP15/PO1, P9 VSS/PP3, P10 PO5/PP5, P11 PP0/PO2, P12 PP7/PP1, P13 PP8/PD9, P14 PD13, P15 PB10, R2 PB1, R3 PF12, R4 PE8, R5 PE10, R7 PP13/PG9, R8 PP4, R9 VSS/PO5, R10 PO4, R11 PP6, R13 PO0/PG10, R14 PP9/PD10
part B pins: A1 VSS, A8 VSS, A11 VSS, A15 VSS, C1 VBAT, D3 VSS, D6 VSS, D8 DVDD, D9 VDD50USB, E3 VSS, E6 VCAP, E8 VSSAUSB, E9 BYPASS_TEST, F6 VSS, F7 VDD, F8 VDD33USB, F9 VDD, F10 VDD, F11 VCAP, F15 VSS, G1 VLXSMPS, G2 VFBSMPS, G6 VDD, G7 VDDLDO, G8 VSS, G9 VDDLDO, G10 VSS, G12 VSS, H1 VDDSMPS, H2 VSSSMPS, H6 VDD, H7 VSS, H8 VSS, H9 VSS, H10 VDD, H11 VSS, H12 VDDOCTO2, J1 VSS, J5 VSSA, J6 VDDA, J7 VDDLDO, J8 VSS, J9 VDDLDO, J10 VSS, J11 VDDOCTO2, J12 VSS, J15 VSS, K4 VREF-, K5 VREF+, K6 VDD, K7 VSS, K8 VDD, K9 VSS, K10 VDD, K11 VCAP, K12 VDDOCTO2, L6 VSS, L7 VCAP, L8 VDDOCTO1, L9 VDD, L10 VDDOCTO1, L11 VSS, M8 VDDOCTO1/VSS, M9 VSS, M10 VDDOCTO1, M15 VSS, R1 VSS, R6 VSS, R12 VSS, R15 VSS

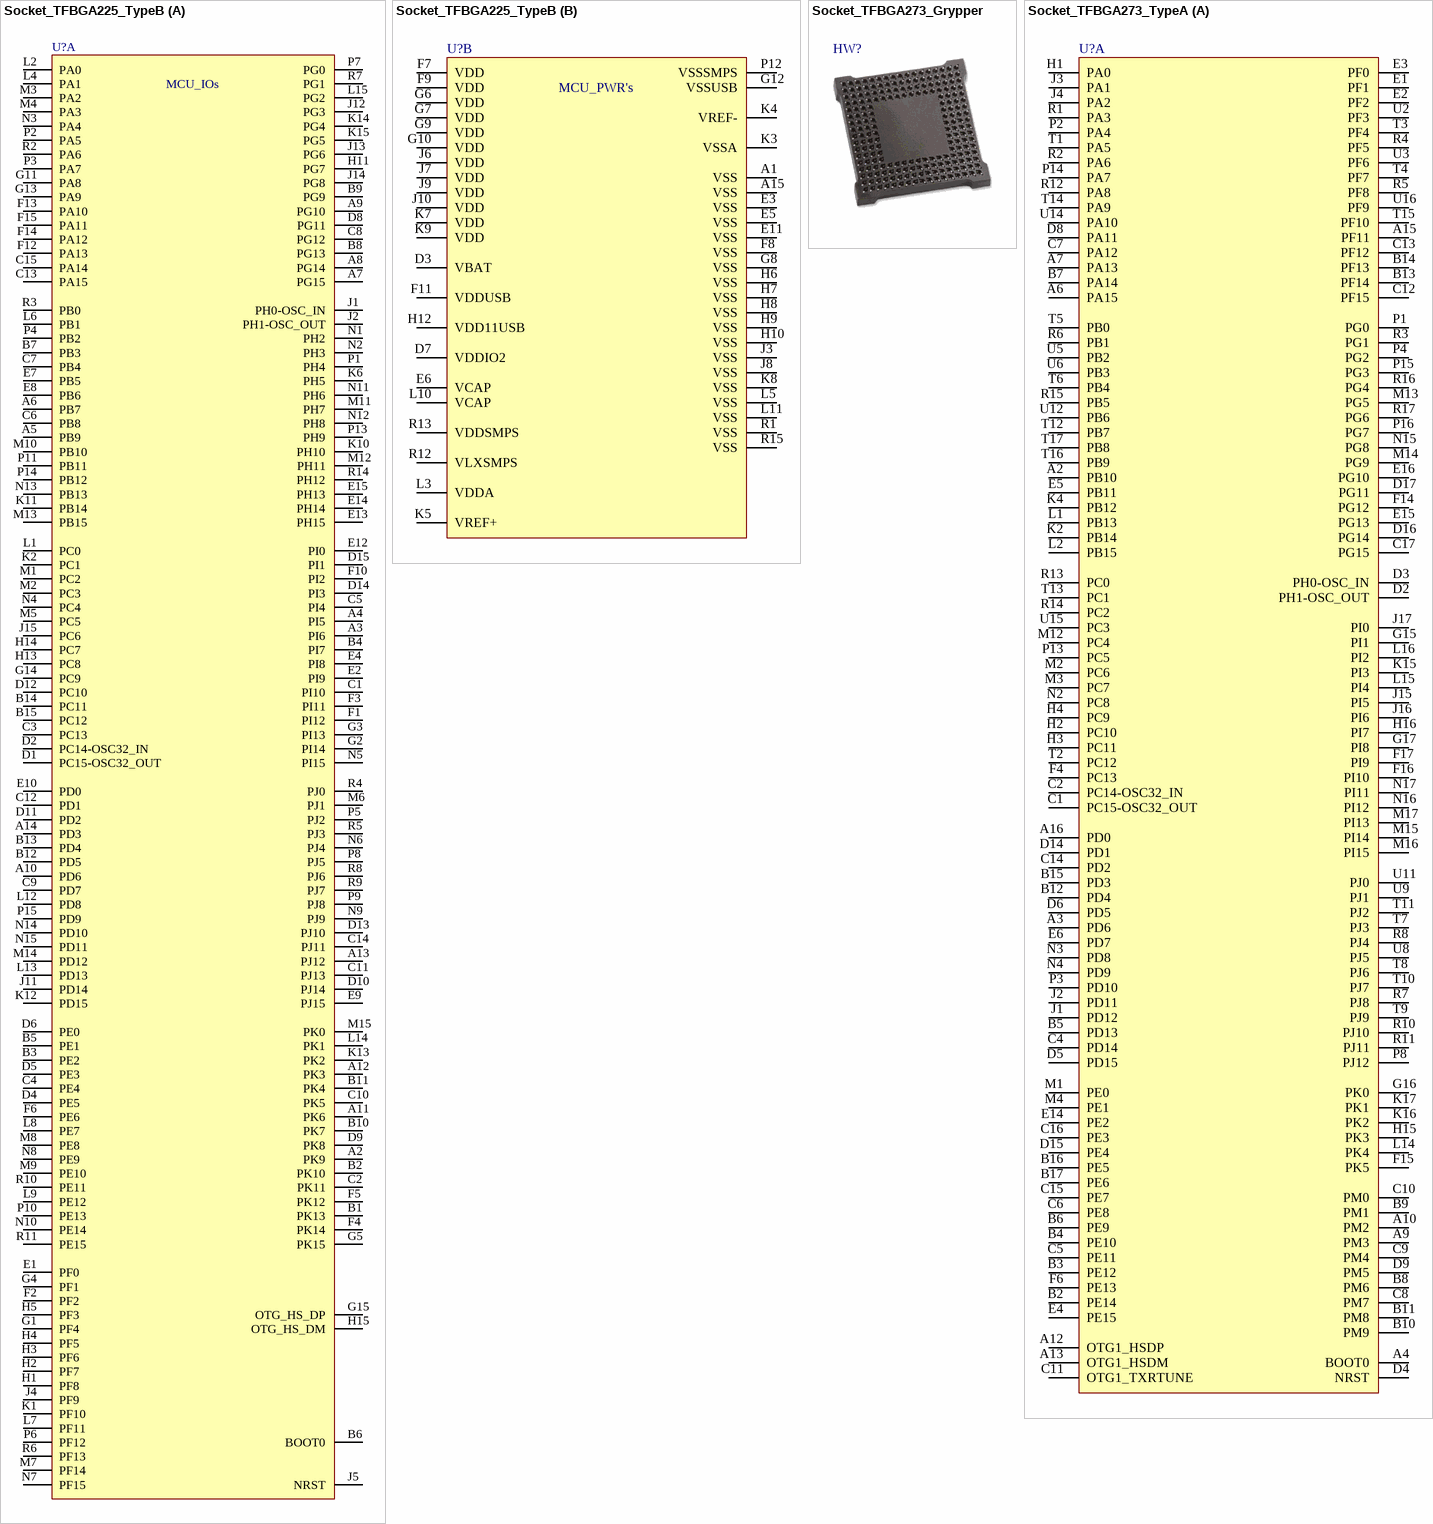
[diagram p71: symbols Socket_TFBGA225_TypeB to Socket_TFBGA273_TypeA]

## Socket_TFBGA225_TypeB
designator U?
part A pins: A2 PK9, A3 PI6, A4 PI5, A5 PB9, A6 PB7, A7 PG15, A8 PG14, A9 PG10, A10 PD6, A11 PK6, A12 PK3, A13 PJ12, A14 PD3, B1 PK13, B2 PK10, B3 PE2, B4 PI7, B5 PE1, B6 BOOT0, B7 PB3, B8 PG13, B9 PG9, B10 PK7, B11 PK4, B12 PD5, B13 PD4, B14 PC11, B15 PC12, C1 PI10, C2 PK11, C3 PC13, C4 PE4, C5 PI4, C6 PB8, C7 PB4, C8 PG12, C9 PD7, C10 PK5, C11 PJ13, C12 PD1, C13 PA15, C14 PJ11, C15 PA14, D1 PC15-OSC32_OUT, D2 PC14-OSC32_IN, D4 PE5, D5 PE3, D6 PE0, D8 PG11, D9 PK8, D10 PJ14, D11 PD2, D12 PC10, D13 PJ10, D14 PI3, D15 PI1, E1 PF0, E2 PI9, E4 PI8, E7 PB5, E8 PB6, E9 PJ15, E10 PD0, E12 PI0, E13 PH15, E14 PH14, E15 PH13, F1 PI12, F2 PF2, F3 PI11, F4 PK14, F5 PK12, F6 PE6, F10 PI2, F12 PA13, F13 PA10, F14 PA12, F15 PA11, G1 PF4, G2 PI14, G3 PI13, G4 PF1, G5 PK15, G11 PA8, G13 PA9, G14 PC9, G15 OTG_HS_DP, H1 PF8, H2 PF7, H3 PF6, H4 PF5, H5 PF3, H11 PG7, H13 PC8, H14 PC7, H15 OTG_HS_DM, J1 PH0-OSC_IN, J2 PH1-OSC_OUT, J4 PF9, J5 NRST, J11 PD14, J12 PG3, J13 PG6, J14 PG8, J15 PC6, K1 PF10, K2 PC1, K6 PH5, K10 PH10, K11 PB14, K12 PD15, K13 PK2, K14 PG4, K15 PG5, L1 PC0, L2 PA0, L4 PA1, L6 PB1, L7 PF11, L8 PE7, L9 PE12, L12 PD8, L13 PD13, L14 PK1, L15 PG2, M1 PC2, M2 PC3, M3 PA2, M4 PA3, M5 PC5, M6 PJ1, M7 PF14, M8 PE8, M9 PE10, M10 PB10, M11 PH7, M12 PH11, M13 PB15, M14 PD12, M15 PK0, N1 PH2, N2 PH3, N3 PA4, N4 PC4, N5 PI15, N6 PJ4, N7 PF15, N8 PE9, N9 PJ9, N10 PE14, N11 PH6, N12 PH8, N13 PB13, N14 PD10, N15 PD11, P1 PH4, P2 PA5, P3 PA7, P4 PB2, P5 PJ2, P6 PF12, P7 PG0, P8 PJ5, P9 PJ8, P10 PE13, P11 PB11, P13 PH9, P14 PB12, P15 PD9, R2 PA6, R3 PB0, R4 PJ0, R5 PJ3, R6 PF13, R7 PG1, R8 PJ6, R9 PJ7, R10 PE11, R11 PE15, R14 PH12
part B pins: A1 VSS, A15 VSS, D3 VBAT, D7 VDDIO2, E3 VSS, E5 VSS, E6 VCAP, E11 VSS, F7 VDD, F8 VSS, F9 VDD, F11 VDDUSB, G6 VDD, G7 VDD, G8 VSS, G9 VDD, G10 VDD, G12 VSSUSB, H6 VSS, H7 VSS, H8 VSS, H9 VSS, H10 VSS, H12 VDD11USB, J3 VSS, J6 VDD, J7 VDD, J8 VSS, J9 VDD, J10 VDD, K3 VSSA, K4 VREF-, K5 VREF+, K7 VDD, K8 VSS, K9 VDD, L3 VDDA, L5 VSS, L10 VCAP, L11 VSS, P12 VSSSMPS, R1 VSS, R12 VLXSMPS, R13 VDDSMPS, R15 VSS

## Socket_TFBGA273_Grypper
designator HW?

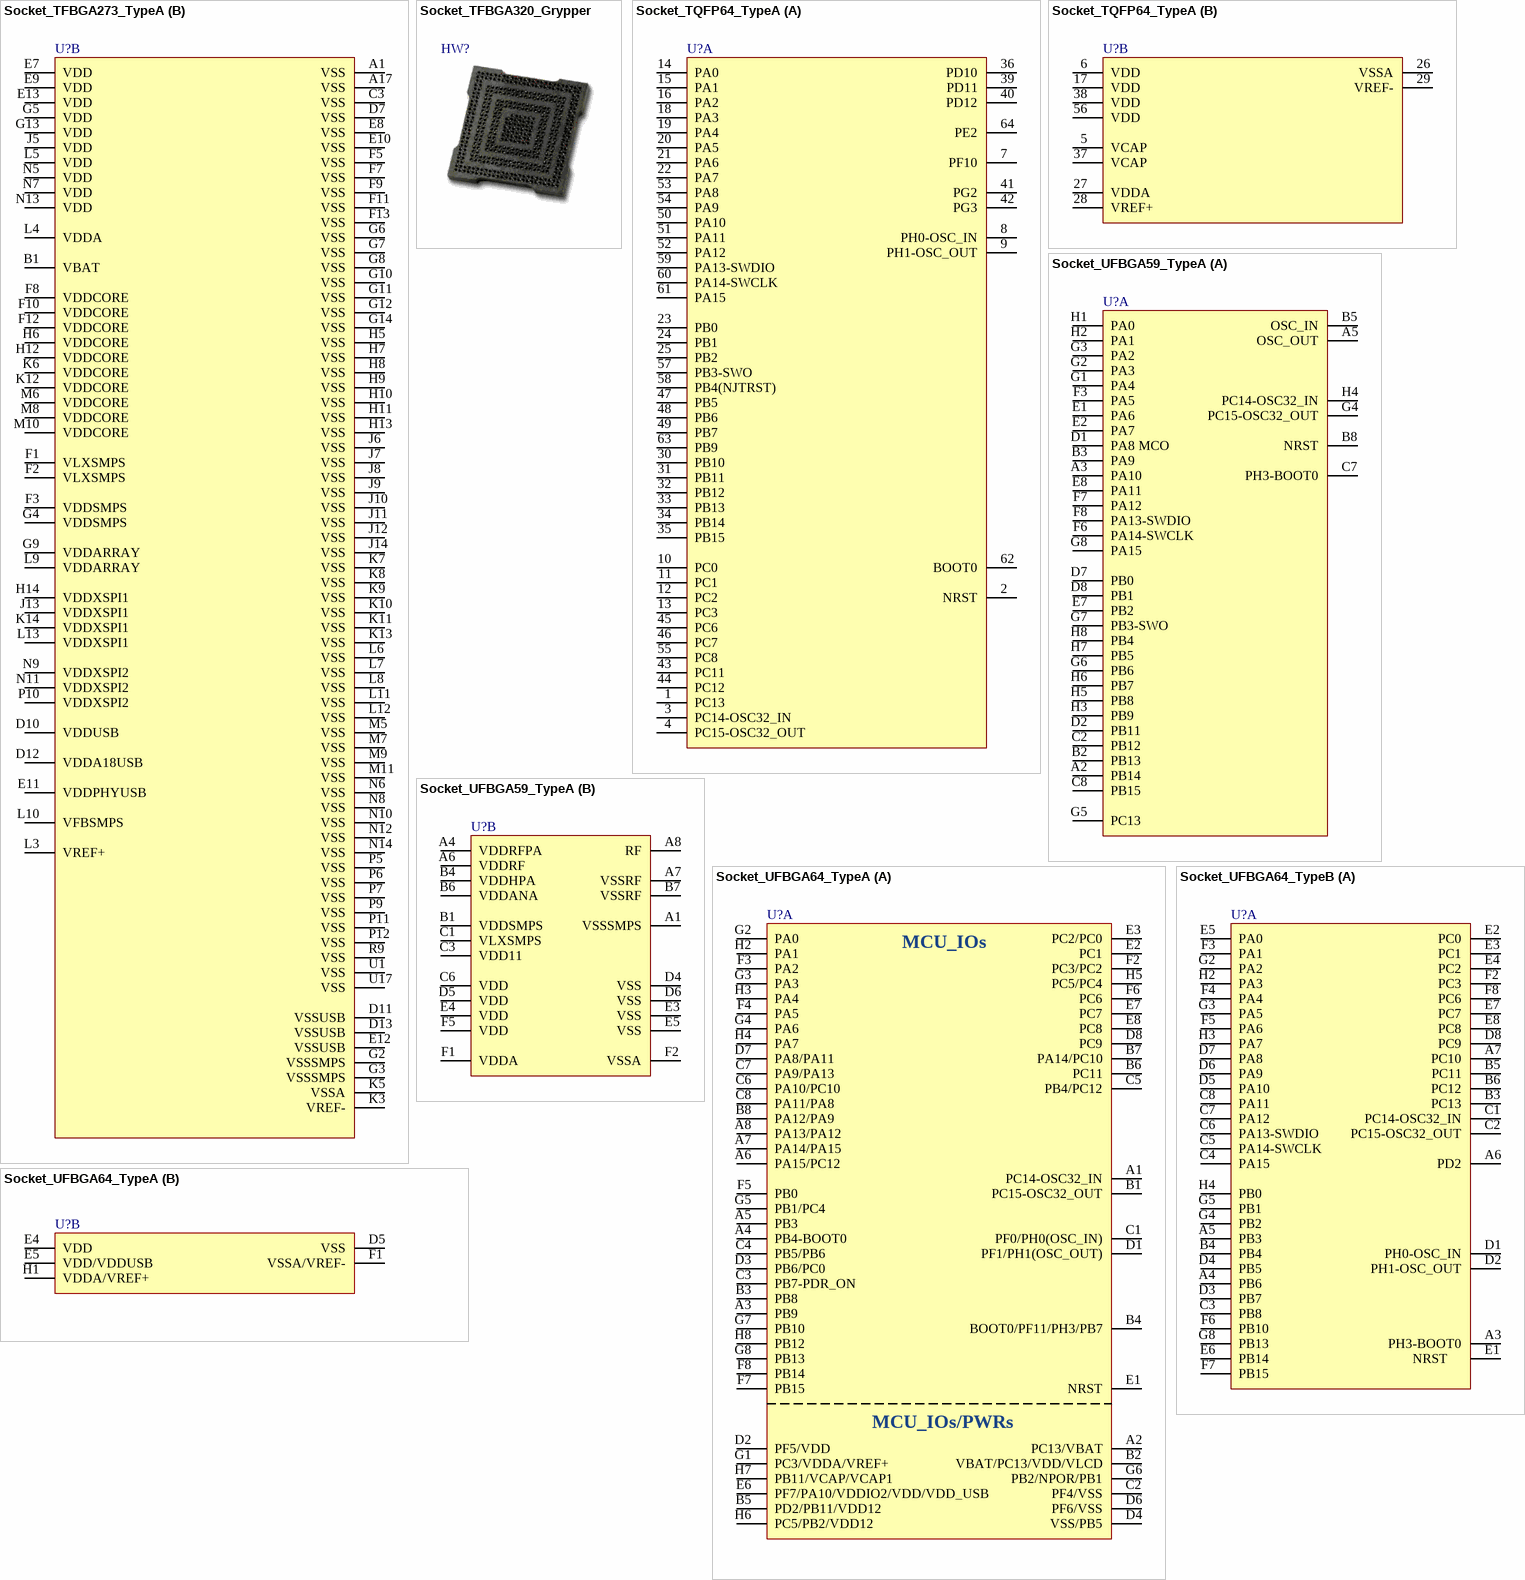
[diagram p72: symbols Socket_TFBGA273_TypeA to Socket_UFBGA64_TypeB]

## Socket_TFBGA273_TypeA
designator U?
part A pins: A2 PB10, A3 PD6, A4 BOOT0, A6 PA15, A7 PA13, A9 PM3, A10 PM2, A12 OTG1_HSDP, A13 OTG1_HSDM, A15 PF11, A16 PD0, B2 PE14, B3 PE12, B4 PE10, B5 PD13, B6 PE9, B7 PA14, B8 PM6, B9 PM1, B10 PM9, B11 PM8, B12 PD4, B13 PF14, B14 PF13, B15 PD3, B16 PE5, B17 PE6, C1 PC15-OSC32_OUT, C2 PC14-OSC32_IN, C4 PD14, C5 PE11, C6 PE8, C7 PA12, C8 PM7, C9 PM4, C10 PM0, C11 OTG1_TXRTUNE, C12 PF15, C13 PF12, C14 PD2, C15 PE7, C16 PE3, C17 PG15, D2 PH1-OSC_OUT, D3 PH0-OSC_IN, D4 NRST, D5 PD15, D6 PD5, D8 PA11, D9 PM5, D14 PD1, D15 PE4, D16 PG14, D17 PG11, E1 PF1, E2 PF2, E3 PF0, E4 PE15, E5 PB11, E6 PD7, E14 PE2, E15 PG13, E16 PG10, F4 PC13, F6 PE13, F14 PG12, F15 PK5, F16 PI10, F17 PI9, G15 PI1, G16 PK0, G17 PI8, H1 PA0, H2 PC10, H3 PC11, H4 PC9, H15 PK3, H16 PI7, J1 PD12, J2 PD11, J3 PA1, J4 PA2, J15 PI5, J16 PI6, J17 PI0, K2 PB14, K4 PB12, K15 PI3, K16 PK2, K17 PK1, L1 PB13, L2 PB15, L14 PK4, L15 PI4, L16 PI2, M1 PE0, M2 PC6, M3 PC7, M4 PE1, M12 PC4, M13 PG5, M14 PG9, M15 PI14, M16 PI15, M17 PI13, N2 PC8, N3 PD8, N4 PD9, N15 PG8, N16 PI12, N17 PI11, P1 PG0, P2 PA4, P3 PD10, P4 PG2, P8 PJ12, P13 PC5, P14 PA7, P15 PG3, P16 PG7, R1 PA3, R2 PA6, R3 PG1, R4 PF5, R5 PF8, R6 PB1, R7 PJ8, R8 PJ4, R10 PJ10, R11 PJ11, R12 PA8, R13 PC0, R14 PC2, R15 PB5, R16 PG4, R17 PG6, T1 PA5, T2 PC12, T3 PF4, T4 PF7, T5 PB0, T6 PB4, T7 PJ3, T8 PJ6, T9 PJ9, T10 PJ7, T11 PJ2, T12 PB7, T13 PC1, T14 PA9, T15 PF10, T16 PB9, T17 PB8, U2 PF3, U3 PF6, U5 PB2, U6 PB3, U8 PJ5, U9 PJ1, U11 PJ0, U12 PB6, U14 PA10, U15 PC3, U16 PF9
part B pins: A1 VSS, A17 VSS, B1 VBAT, C3 VSS, D7 VSS, D10 VDDUSB, D11 VSSUSB, D12 VDDA18USB, D13 VSSUSB, E7 VDD, E8 VSS, E9 VDD, E10 VSS, E11 VDDPHYUSB, E12 VSSUSB, E13 VDD, F1 VLXSMPS, F2 VLXSMPS, F3 VDDSMPS, F5 VSS, F7 VSS, F8 VDDCORE, F9 VSS, F10 VDDCORE, F11 VSS, F12 VDDCORE, F13 VSS, G2 VSSSMPS, G3 VSSSMPS, G4 VDDSMPS, G5 VDD, G6 VSS, G7 VSS, G8 VSS, G9 VDDARRAY, G10 VSS, G11 VSS, G12 VSS, G13 VDD, G14 VSS, H5 VSS, H6 VDDCORE, H7 VSS, H8 VSS, H9 VSS, H10 VSS, H11 VSS, H12 VDDCORE, H13 VSS, H14 VDDXSPI1, J5 VDD, J6 VSS, J7 VSS, J8 VSS, J9 VSS, J10 VSS, J11 VSS, J12 VSS, J13 VDDXSPI1, J14 VSS, K3 VREF-, K5 VSSA, K6 VDDCORE, K7 VSS, K8 VSS, K9 VSS, K10 VSS, K11 VSS, K12 VDDCORE, K13 VSS, K14 VDDXSPI1, L3 VREF+, L4 VDDA, L5 VDD, L6 VSS, L7 VSS, L8 VSS, L9 VDDARRAY, L10 VFBSMPS, L11 VSS, L12 VSS, L13 VDDXSPI1, M5 VSS, M6 VDDCORE, M7 VSS, M8 VDDCORE, M9 VSS, M10 VDDCORE, M11 VSS, N5 VDD, N6 VSS, N7 VDD, N8 VSS, N9 VDDXSPI2, N10 VSS, N11 VDDXSPI2, N12 VSS, N13 VDD, N14 VSS, P5 VSS, P6 VSS, P7 VSS, P9 VSS, P10 VDDXSPI2, P11 VSS, P12 VSS, R9 VSS, U1 VSS, U17 VSS

## Socket_TFBGA320_Grypper
designator HW?

## Socket_TQFP64_TypeA
designator U?
part A pins: 1 PC13, 2 NRST, 3 PC14-OSC32_IN, 4 PC15-OSC32_OUT, 7 PF10, 8 PH0-OSC_IN, 9 PH1-OSC_OUT, 10 PC0, 11 PC1, 12 PC2, 13 PC3, 14 PA0, 15 PA1, 16 PA2, 18 PA3, 19 PA4, 20 PA5, 21 PA6, 22 PA7, 23 PB0, 24 PB1, 25 PB2, 30 PB10, 31 PB11, 32 PB12, 33 PB13, 34 PB14, 35 PB15, 36 PD10, 39 PD11, 40 PD12, 41 PG2, 42 PG3, 43 PC11, 44 PC12, 45 PC6, 46 PC7, 47 PB5, 48 PB6, 49 PB7, 50 PA10, 51 PA11, 52 PA12, 53 PA8, 54 PA9, 55 PC8, 57 PB3-SWO, 58 PB4(NJTRST), 59 PA13-SWDIO, 60 PA14-SWCLK, 61 PA15, 62 BOOT0, 63 PB9, 64 PE2
part B pins: 5 VCAP, 6 VDD, 17 VDD, 26 VSSA, 27 VDDA, 28 VREF+, 29 VREF-, 37 VCAP, 38 VDD, 56 VDD

## Socket_UFBGA59_TypeA
designator U?
part A pins: A2 PB14, A3 PA10, A5 OSC_OUT, B2 PB13, B3 PA9, B5 OSC_IN, B8 NRST, C2 PB12, C7 PH3-BOOT0, C8 PB15, D1 PA8 MCO, D2 PB11, D7 PB0, D8 PB1, E1 PA6, E2 PA7, E7 PB2, E8 PA11, F3 PA5, F6 PA14-SWCLK, F7 PA12, F8 PA13-SWDIO, G1 PA4, G2 PA3, G3 PA2, G4 PC15-OSC32_OUT, G5 PC13, G6 PB6, G7 PB3-SWO, G8 PA15, H1 PA0, H2 PA1, H3 PB9, H4 PC14-OSC32_IN, H5 PB8, H6 PB7, H7 PB5, H8 PB4
part B pins: A1 VSSSMPS, A4 VDDRFPA, A6 VDDRF, A7 VSSRF, A8 RF, B1 VDDSMPS, B4 VDDHPA, B6 VDDANA, B7 VSSRF, C1 VLXSMPS, C3 VDD11, C6 VDD, D4 VSS, D5 VDD, D6 VSS, E3 VSS, E4 VDD, E5 VSS, F1 VDDA, F2 VSSA, F5 VDD

## Socket_UFBGA64_TypeA
designator U?
part A pins: A1 PC14-OSC32_IN, A2 PC13/VBAT, A3 PB9, A4 PB4-BOOT0, A5 PB3, A6 PA15/PC12, A7 PA14/PA15, A8 PA13/PA12, B1 PC15-OSC32_OUT, B2 VBAT/PC13/VDD/VLCD, B3 PB8, B4 BOOT0/PF11/PH3/PB7, B5 PD2/PB11/VDD12, B6 PC11, B7 PA14/PC10, B8 PA12/PA9, C1 PF0/PH0(OSC_IN), C2 PF4/VSS, C3 PB7-PDR_ON, C4 PB5/PB6, C5 PB4/PC12, C6 PA10/PC10, C7 PA9/PA13, C8 PA11/PA8, D1 PF1/PH1(OSC_OUT), D2 PF5/VDD, D3 PB6/PC0, D4 VSS/PB5, D6 PF6/VSS, D7 PA8/PA11, D8 PC9, E1 NRST, E2 PC1, E3 PC2/PC0, E6 PF7/PA10/VDDIO2/VDD/VDD_USB, E7 PC7, E8 PC8, F2 PC3/PC2, F3 PA2, F4 PA5, F5 PB0, F6 PC6, F7 PB15, F8 PB14, G1 PC3/VDDA/VREF+, G2 PA0, G3 PA3, G4 PA6, G5 PB1/PC4, G6 PB2/NPOR/PB1, G7 PB10, G8 PB13, H2 PA1, H3 PA4, H4 PA7, H5 PC5/PC4, H6 PC5/PB2/VDD12, H7 PB11/VCAP/VCAP1, H8 PB12
part B pins: D5 VSS, E4 VDD, E5 VDD/VDDUSB, F1 VSSA/VREF-, H1 VDDA/VREF+

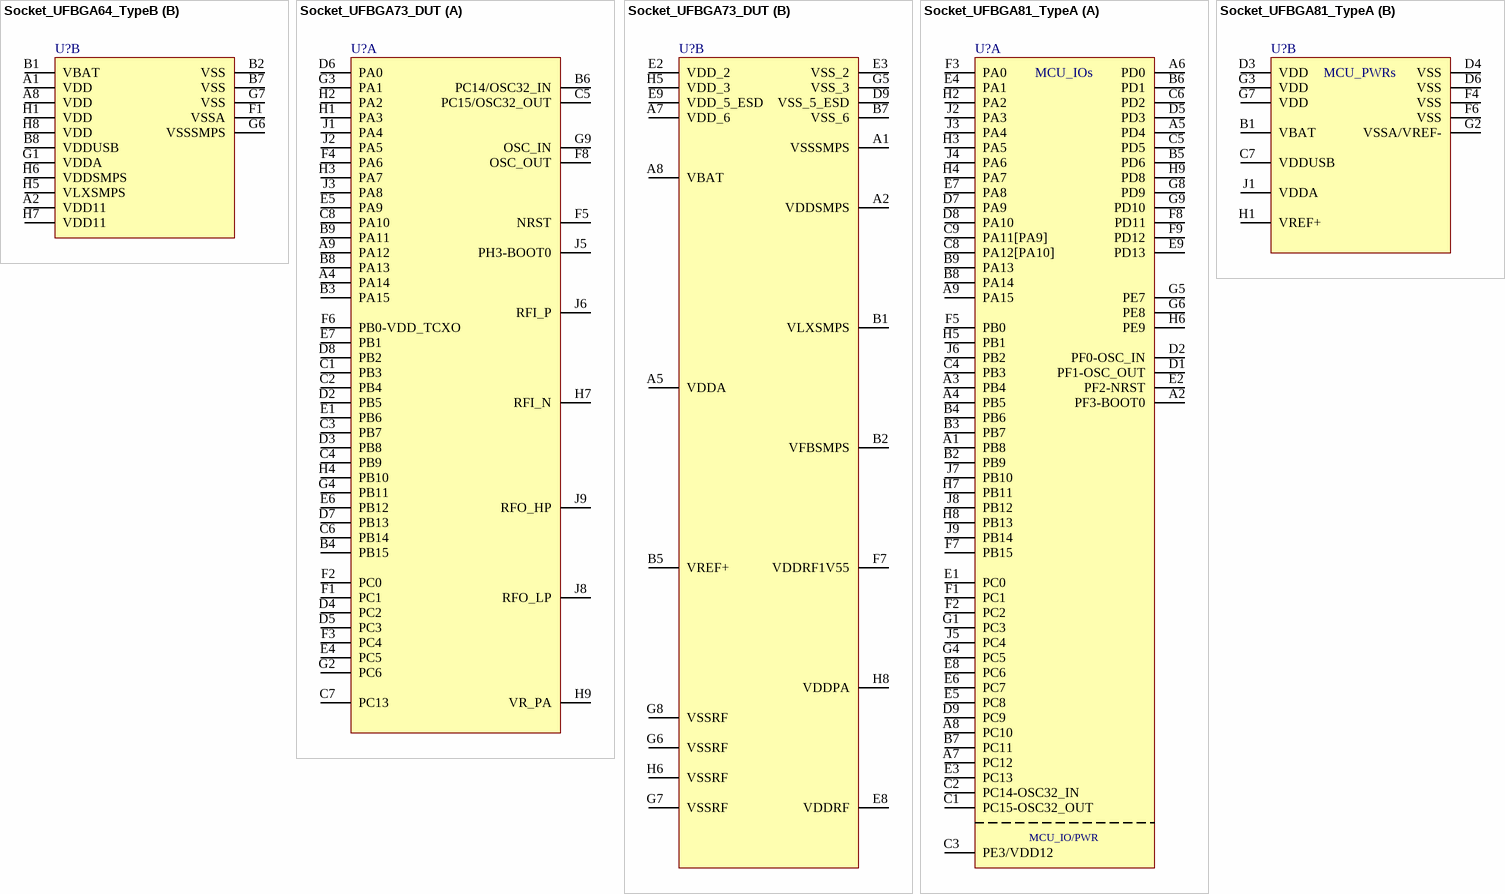
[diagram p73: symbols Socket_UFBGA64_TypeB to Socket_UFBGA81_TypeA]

## Socket_UFBGA64_TypeB
designator U?
part A pins: A3 PH3-BOOT0, A4 PB6, A5 PB3, A6 PD2, A7 PC10, B3 PC13, B4 PB4, B5 PC11, B6 PC12, C1 PC14-OSC32_IN, C2 PC15-OSC32_OUT, C3 PB8 , C4 PA15, C5 PA14-SWCLK, C6 PA13-SWDIO, C7 PA12, C8 PA11, D1 PH0-OSC_IN, D2 PH1-OSC_OUT, D3 PB7, D4 PB5, D5 PA10, D6 PA9, D7 PA8, D8 PC9, E1 NRST    , E2 PC0, E3 PC1, E4 PC2, E5 PA0, E6 PB14, E7 PC7, E8 PC8, F2 PC3, F3 PA1, F4 PA4, F5 PA6, F6 PB10, F7 PB15, F8 PC6, G2 PA2, G3 PA5, G4 PB2, G5 PB1, G8 PB13, H2 PA3, H3 PA7, H4 PB0
part B pins: A1 VDD, A2 VDD11, A8 VDD, B1 VBAT, B2 VSS, B7 VSS, B8 VDDUSB, F1 VSSA, G1 VDDA, G6 VSSSMPS, G7 VSS, H1 VDD, H5 VLXSMPS, H6 VDDSMPS, H7 VDD11, H8 VDD

## Socket_UFBGA73_DUT
designator U?
part A pins: A4 PA14, A9 PA12, B3 PA15, B4 PB15, B6 PC14/OSC32_IN, B8 PA13, B9 PA11, C1 PB3, C2 PB4, C3 PB7, C4 PB9, C5 PC15/OSC32_OUT, C6 PB14, C7 PC13, C8 PA10, D2 PB5, D3 PB8, D4 PC2, D5 PC3, D6 PA0, D7 PB13, D8 PB2, E1 PB6, E4 PC5, E5 PA9, E6 PB12, E7 PB1, F1 PC1, F2 PC0, F3 PC4, F4 PA6, F5 NRST, F6 PB0-VDD_TCXO, F8 OSC_OUT, G2 PC6, G3 PA1, G4 PB11, G9 OSC_IN, H1 PA3, H2 PA2, H3 PA7, H4 PB10, H7 RFI_N, H9 VR_PA, J1 PA4, J2 PA5, J3 PA8, J5 PH3-BOOT0, J6 RFI_P, J8 RFO_LP, J9 RFO_HP
part B pins: A1 VSSSMPS, A2 VDDSMPS, A5 VDDA, A7 VDD_6, A8 VBAT, B1 VLXSMPS, B2 VFBSMPS, B5 VREF+, B7 VSS_6, D9 VSS_5_ESD, E2 VDD_2, E3 VSS_2, E8 VDDRF, E9 VDD_5_ESD, F7 VDDRF1V55, G5 VSS_3, G6 VSSRF, G7 VSSRF, G8 VSSRF, H5 VDD_3, H6 VSSRF, H8 VDDPA

## Socket_UFBGA81_TypeA
designator U?
part A pins: A1 PB8, A2 PF3-BOOT0, A3 PB4, A4 PB5, A5 PD4, A6 PD0, A7 PC12, A8 PC10, A9 PA15, B2 PB9, B3 PB7, B4 PB6, B5 PD6, B6 PD1, B7 PC11, B8 PA14, B9 PA13, C1 PC15-OSC32_OUT, C2 PC14-OSC32_IN, C3 PE3/VDD12, C4 PB3, C5 PD5, C6 PD2, C8 PA12[PA10], C9 PA11[PA9], D1 PF1-OSC_OUT, D2 PF0-OSC_IN, D5 PD3, D7 PA9, D8 PA10, D9 PC9, E1 PC0, E2 PF2-NRST, E3 PC13, E4 PA1, E5 PC8, E6 PC7, E7 PA8, E8 PC6, E9 PD13, F1 PC1, F2 PC2, F3 PA0, F5 PB0, F7 PB15, F8 PD11, F9 PD12, G1 PC3, G4 PC5, G5 PE7, G6 PE8, G8 PD9, G9 PD10, H2 PA2, H3 PA5, H4 PA7, H5 PB1, H6 PE9, H7 PB11, H8 PB13, H9 PD8, J2 PA3, J3 PA4, J4 PA6, J5 PC4, J6 PB2, J7 PB10, J8 PB12, J9 PB14
part B pins: B1 VBAT, C7 VDDUSB, D3 VDD, D4 VSS, D6 VSS, F4 VSS, F6 VSS, G2 VSSA/VREF-, G3 VDD, G7 VDD, H1 VREF+, J1 VDDA

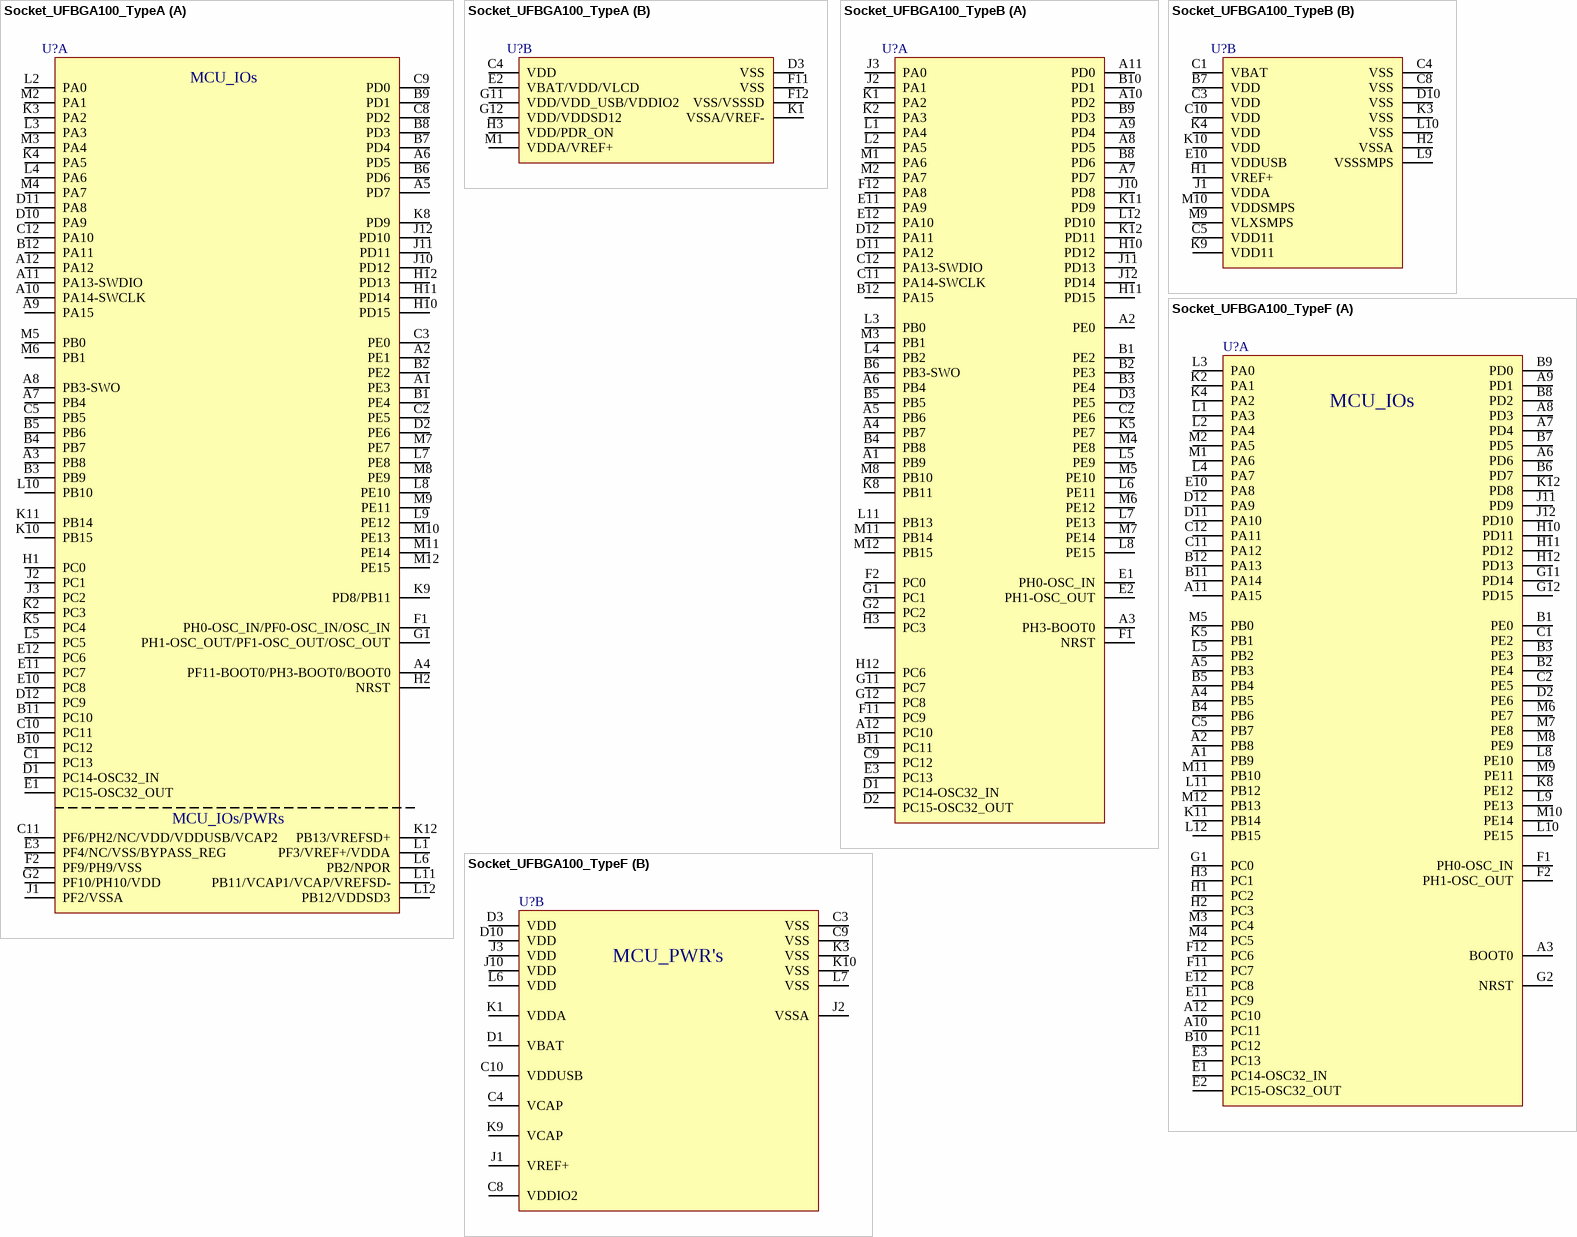
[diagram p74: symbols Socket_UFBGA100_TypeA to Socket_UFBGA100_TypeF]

## Socket_UFBGA100_TypeA
designator U?
part A pins: A1 PE3, A2 PE1, A3 PB8, A4 PF11-BOOT0/PH3-BOOT0/BOOT0, A5 PD7, A6 PD5, A7 PB4, A8 PB3-SWO, A9 PA15, A10 PA14-SWCLK, A11 PA13-SWDIO, A12 PA12, B1 PE4, B2 PE2, B3 PB9, B4 PB7, B5 PB6, B6 PD6, B7 PD4, B8 PD3, B9 PD1, B10 PC12, B11 PC10, B12 PA11, C1 PC13, C2 PE5, C3 PE0, C5 PB5, C8 PD2, C9 PD0, C10 PC11, C11 PF6/PH2/NC/VDD/VDDUSB/VCAP2, C12 PA10, D1 PC14-OSC32_IN, D2 PE6, D10 PA9, D11 PA8, D12 PC9, E1 PC15-OSC32_OUT, E3 PF4/NC/VSS/BYPASS_REG, E10 PC8, E11 PC7, E12 PC6, F1 PH0-OSC_IN/PF0-OSC_IN/OSC_IN, F2 PF9/PH9/VSS, G1 PH1-OSC_OUT/PF1-OSC_OUT/OSC_OUT, G2 PF10/PH10/VDD, H1 PC0, H2 NRST, H10 PD15, H11 PD14, H12 PD13, J1 PF2/VSSA, J2 PC1, J3 PC2, J10 PD12, J11 PD11, J12 PD10, K2 PC3, K3 PA2, K4 PA5, K5 PC4, K8 PD9, K9 PD8/PB11, K10 PB15, K11 PB14, K12 PB13/VREFSD+, L1 PF3/VREF+/VDDA, L2 PA0, L3 PA3, L4 PA6, L5 PC5, L6 PB2/NPOR, L7 PE8, L8 PE10, L9 PE12, L10 PB10, L11 PB11/VCAP1/VCAP/VREFSD-, L12 PB12/VDDSD3, M2 PA1, M3 PA4, M4 PA7, M5 PB0, M6 PB1, M7 PE7, M8 PE9, M9 PE11, M10 PE13, M11 PE14, M12 PE15
part B pins: C4 VDD, D3 VSS, E2 VBAT/VDD/VLCD, F11 VSS, F12 VSS/VSSSD, G11 VDD/VDD_USB/VDDIO2, G12 VDD/VDDSD12, H3 VDD/PDR_ON, K1 VSSA/VREF-, M1 VDDA/VREF+

## Socket_UFBGA100_TypeB
designator U?
part A pins: A1 PB9, A2 PE0, A3 PH3-BOOT0, A4 PB7, A5 PB6, A6 PB4, A7 PD7, A8 PD5, A9 PD4, A10 PD2, A11 PD0, A12 PC10, B1 PE2, B2 PE3, B3 PE4, B4 PB8, B5 PB5, B6 PB3-SWO, B8 PD6, B9 PD3, B10 PD1, B11 PC11, B12 PA15, C2 PE6, C9 PC12, C11 PA14-SWCLK, C12 PA13-SWDIO, D1 PC14-OSC32_IN, D2 PC15-OSC32_OUT, D3 PE5, D11 PA12, D12 PA11, E1 PH0-OSC_IN, E2 PH1-OSC_OUT, E3 PC13, E11 PA9, E12 PA10, F1 NRST, F2 PC0, F11 PC9, F12 PA8, G1 PC1, G2 PC2, G11 PC7, G12 PC8, H3 PC3, H10 PD12, H11 PD15, H12 PC6, J2 PA1, J3 PA0, J10 PD8, J11 PD13, J12 PD14, K1 PA2, K2 PA3, K5 PE7, K8 PB11, K11 PD9, K12 PD11, L1 PA4, L2 PA5, L3 PB0, L4 PB2, L5 PE9, L6 PE11, L7 PE13, L8 PE15, L11 PB13, L12 PD10, M1 PA6, M2 PA7, M3 PB1, M4 PE8, M5 PE10, M6 PE12, M7 PE14, M8 PB10, M11 PB14, M12 PB15
part B pins: B7 VDD, C1 VBAT, C3 VDD, C4 VSS, C5 VDD11, C8 VSS, C10 VDD, D10 VSS, E10 VDDUSB, H1 VREF+, H2 VSSA, J1 VDDA, K3 VSS, K4 VDD, K9 VDD11, K10 VDD, L9 VSSSMPS, L10 VSS, M9 VLXSMPS, M10 VDDSMPS

## Socket_UFBGA100_TypeF
designator U?
part A pins: A1 PB9, A2 PB8, A3 BOOT0, A4 PB5, A5 PB3, A6 PD6, A7 PD4, A8 PD3, A9 PD1, A10 PC11, A11 PA15, A12 PC10, B1 PE0, B2 PE4, B3 PE3, B4 PB6, B5 PB4, B6 PD7, B7 PD5, B8 PD2, B9 PD0, B10 PC12, B11 PA14, B12 PA13, C1 PE2, C2 PE5, C5 PB7, C11 PA12, C12 PA11, D2 PE6, D11 PA10, D12 PA9, E1 PC14-OSC32_IN, E2 PC15-OSC32_OUT, E3 PC13, E10 PA8, E11 PC9, E12 PC8, F1 PH0-OSC_IN, F2 PH1-OSC_OUT, F11 PC7, F12 PC6, G1 PC0, G2 NRST, G11 PD14, G12 PD15, H1 PC2, H2 PC3, H3 PC1, H10 PD11, H11 PD12, H12 PD13, J11 PD9, J12 PD10, K2 PA1, K4 PA2, K5 PB1, K8 PE12, K11 PB14, K12 PD8, L1 PA3, L2 PA4, L3 PA0, L4 PA7, L5 PB2, L8 PE10, L9 PE13, L10 PE15, L11 PB12, L12 PB15, M1 PA6, M2 PA5, M3 PC4, M4 PC5, M5 PB0, M6 PE7, M7 PE8, M8 PE9, M9 PE11, M10 PE14, M11 PB10, M12 PB13
part B pins: C3 VSS, C4 VCAP, C8 VDDIO2, C9 VSS, C10 VDDUSB, D1 VBAT, D3 VDD, D10 VDD, J1 VREF+, J2 VSSA, J3 VDD, J10 VDD, K1 VDDA, K3 VSS, K9 VCAP, K10 VSS, L6 VDD, L7 VSS

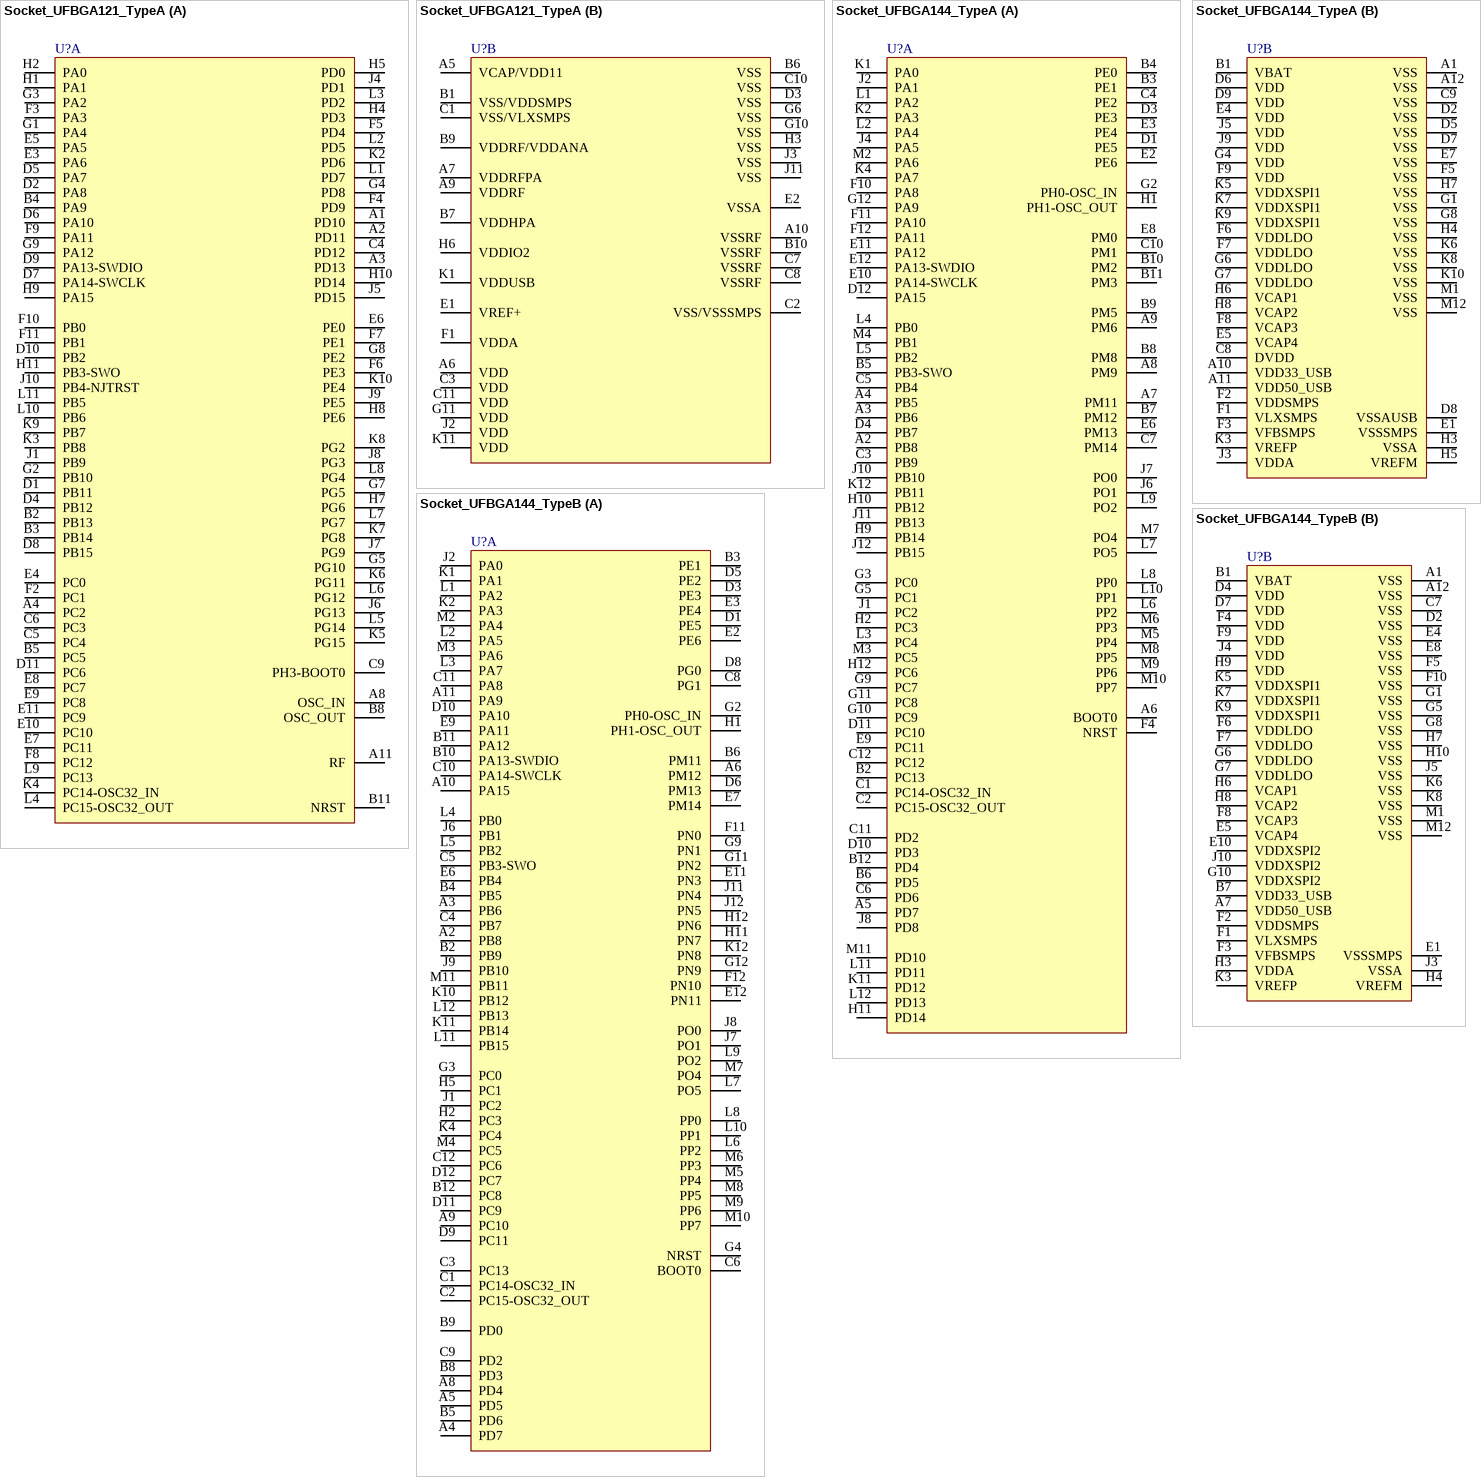
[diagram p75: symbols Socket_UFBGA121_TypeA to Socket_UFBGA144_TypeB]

## Socket_UFBGA121_TypeA
designator U?
part A pins: A1 PD10, A2 PD11, A3 PD13, A4 PC2, A8 OSC_IN, A11 RF, B2 PB13, B3 PB14, B4 PA9, B5 PC5, B8 OSC_OUT, B11 NRST, C4 PD12, C5 PC4, C6 PC3, C9 PH3-BOOT0, D1 PB11, D2 PA8, D4 PB12, D5 PA7, D6 PA10, D7 PA14-SWCLK, D8 PB15, D9 PA13-SWDIO, D10 PB2, D11 PC6, E3 PA6, E4 PC0, E5 PA5, E6 PE0, E7 PC11, E8 PC7, E9 PC8, E10 PC10, E11 PC9, F2 PC1, F3 PA3, F4 PD9, F5 PD4, F6 PE3, F7 PE1, F8 PC12, F9 PA11, F10 PB0, F11 PB1, G1 PA4, G2 PB10, G3 PA2, G4 PD8, G5 PG10, G7 PG5, G8 PE2, G9 PA12, H1 PA1, H2 PA0, H4 PD3, H5 PD0, H7 PG6, H8 PE6, H9 PA15, H10 PD14, H11 PB3-SWO, J1 PB9, J4 PD1, J5 PD15, J6 PG13, J7 PG9, J8 PG3, J9 PE5, J10 PB4-NJTRST, K2 PD6, K3 PB8, K4 PC14-OSC32_IN, K5 PG15, K6 PG11, K7 PG8, K8 PG2, K9 PB7, K10 PE4, L1 PD7, L2 PD5, L3 PD2, L4 PC15-OSC32_OUT, L5 PG14, L6 PG12, L7 PG7, L8 PG4, L9 PC13, L10 PB6, L11 PB5
part B pins: A5 VCAP/VDD11, A6 VDD, A7 VDDRFPA, A9 VDDRF, A10 VSSRF, B1 VSS/VDDSMPS, B6 VSS, B7 VDDHPA, B9 VDDRF/VDDANA, B10 VSSRF, C1 VSS/VLXSMPS, C2 VSS/VSSSMPS, C3 VDD, C7 VSSRF, C8 VSSRF, C10 VSS, C11 VDD, D3 VSS, E1 VREF+, E2 VSSA, F1 VDDA, G6 VSS, G10 VSS, G11 VDD, H3 VSS, H6 VDDIO2, J2 VDD, J3 VSS, J11 VSS, K1 VDDUSB, K11 VDD

## Socket_UFBGA144_TypeA
designator U?
part A pins: A2 PB8, A3 PB6, A4 PB5, A5 PD7, A6 BOOT0, A7 PM11, A8 PM9, A9 PM6, B2 PC13, B3 PE1, B4 PE0, B5 PB3-SWO, B6 PD5, B7 PM12, B8 PM8, B9 PM5, B10 PM2, B11 PM3, B12 PD4, C1 PC14-OSC32_IN, C2 PC15-OSC32_OUT, C3 PB9, C4 PE2, C5 PB4, C6 PD6, C7 PM14, C10 PM1, C11 PD2, C12 PC12, D1 PE5, D3 PE3, D4 PB7, D10 PD3, D11 PC10, D12 PA15, E2 PE6, E3 PE4, E6 PM13, E8 PM0, E9 PC11, E10 PA14-SWCLK, E11 PA12, E12 PA13-SWDIO, F4 NRST, F10 PA8, F11 PA10, F12 PA11, G2 PH0-OSC_IN, G3 PC0, G5 PC1, G9 PC7, G10 PC9, G11 PC8, G12 PA9, H1 PH1-OSC_OUT, H2 PC3, H9 PB14, H10 PB12, H11 PD14, H12 PC6, J1 PC2, J2 PA1, J4 PA5, J6 PO1, J7 PO0, J8 PD8, J10 PB10, J11 PB13, J12 PB15, K1 PA0, K2 PA3, K4 PA7, K11 PD12, K12 PB11, L1 PA2, L2 PA4, L3 PC4, L4 PB0, L5 PB2, L6 PP2, L7 PO5, L8 PP0, L9 PO2, L10 PP1, L11 PD11, L12 PD13, M2 PA6, M3 PC5, M4 PB1, M5 PP4, M6 PP3, M7 PO4, M8 PP5, M9 PP6, M10 PP7, M11 PD10
part B pins: A1 VSS, A10 VDD33_USB, A11 VDD50_USB, A12 VSS, B1 VBAT, C8 DVDD, C9 VSS, D2 VSS, D5 VSS, D6 VDD, D7 VSS, D8 VSSAUSB, D9 VDD, E1 VSSSMPS, E4 VDD, E5 VCAP4, E7 VSS, F1 VLXSMPS, F2 VDDSMPS, F3 VFBSMPS, F5 VSS, F6 VDDLDO, F7 VDDLDO, F8 VCAP3, F9 VDD, G1 VSS, G4 VDD, G6 VDDLDO, G7 VDDLDO, G8 VSS, H3 VSSA, H4 VSS, H5 VREFM, H6 VCAP1, H7 VSS, H8 VCAP2, J3 VDDA, J5 VDD, J9 VDD, K3 VREFP, K5 VDDXSPI1, K6 VSS, K7 VDDXSPI1, K8 VSS, K9 VDDXSPI1, K10 VSS, M1 VSS, M12 VSS

## Socket_UFBGA144_TypeB
designator U?
part A pins: A2 PB8, A3 PB6, A4 PD7, A5 PD5, A6 PM12, A8 PD4, A9 PC10, A10 PA15, A11 PA9, B2 PB9, B3 PE1, B4 PB5, B5 PD6, B6 PM11, B8 PD3, B9 PD0, B10 PA13-SWDIO, B11 PA12, B12 PC8, C1 PC14-OSC32_IN, C2 PC15-OSC32_OUT, C3 PC13, C4 PB7, C5 PB3-SWO, C6 BOOT0, C8 PG1, C9 PD2, C10 PA14-SWCLK, C11 PA8, C12 PC6, D1 PE5, D3 PE3, D5 PE2, D6 PM13, D8 PG0, D9 PC11, D10 PA10, D11 PC9, D12 PC7, E2 PE6, E3 PE4, E6 PB4, E7 PM14, E9 PA11, E11 PN3, E12 PN11, F11 PN0, F12 PN10, G2 PH0-OSC_IN, G3 PC0, G4 NRST, G9 PN1, G11 PN2, G12 PN9, H1 PH1-OSC_OUT, H2 PC3, H5 PC1, H11 PN7, H12 PN6, J1 PC2, J2 PA0, J6 PB1, J7 PO1, J8 PO0, J9 PB10, J11 PN4, J12 PN5, K1 PA1, K2 PA3, K4 PC4, K10 PB12, K11 PB14, K12 PN8, L1 PA2, L2 PA5, L3 PA7, L4 PB0, L5 PB2, L6 PP2, L7 PO5, L8 PP0, L9 PO2, L10 PP1, L11 PB15, L12 PB13, M2 PA4, M3 PA6, M4 PC5, M5 PP4, M6 PP3, M7 PO4, M8 PP5, M9 PP6, M10 PP7, M11 PB11
part B pins: A1 VSS, A7 VDD50_USB, A12 VSS, B1 VBAT, B7 VDD33_USB, C7 VSS, D2 VSS, D4 VDD, D7 VDD, E1 VSSSMPS, E4 VSS, E5 VCAP4, E8 VSS, E10 VDDXSPI2, F1 VLXSMPS, F2 VDDSMPS, F3 VFBSMPS, F4 VDD, F5 VSS, F6 VDDLDO, F7 VDDLDO, F8 VCAP3, F9 VDD, F10 VSS, G1 VSS, G5 VSS, G6 VDDLDO, G7 VDDLDO, G8 VSS, G10 VDDXSPI2, H3 VDDA, H4 VREFM, H6 VCAP1, H7 VSS, H8 VCAP2, H9 VDD, H10 VSS, J3 VSSA, J4 VDD, J5 VSS, J10 VDDXSPI2, K3 VREFP, K5 VDDXSPI1, K6 VSS, K7 VDDXSPI1, K8 VSS, K9 VDDXSPI1, M1 VSS, M12 VSS

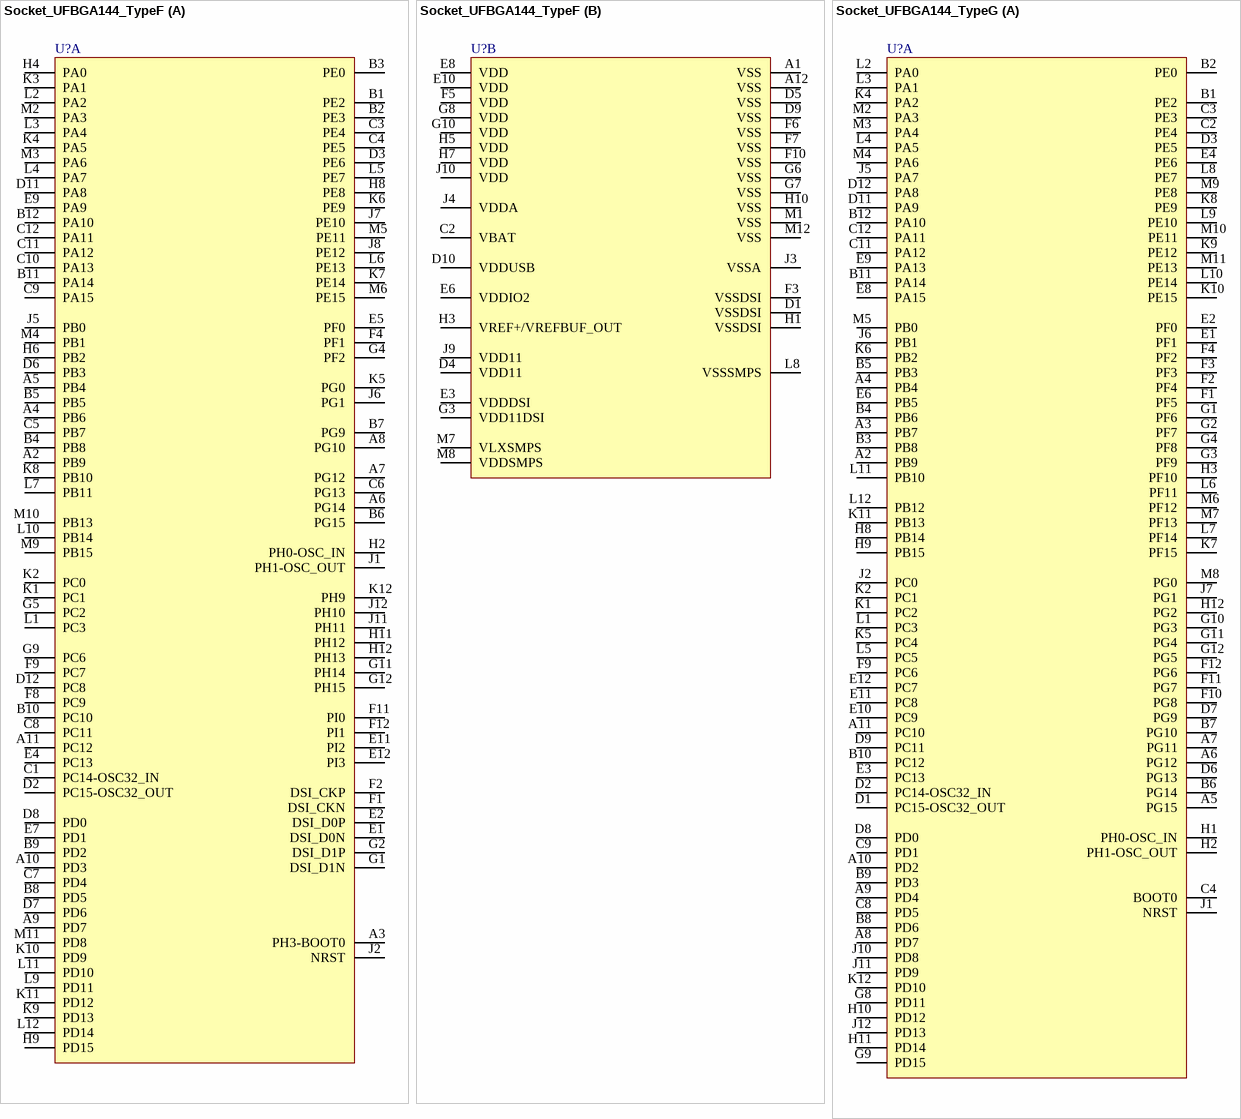
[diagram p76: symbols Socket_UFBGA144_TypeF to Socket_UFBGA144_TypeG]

## Socket_UFBGA144_TypeF
designator U?
part A pins: A2 PB9, A3 PH3-BOOT0, A4 PB6, A5 PB4, A6 PG14, A7 PG12, A8 PG10, A9 PD7, A10 PD3, A11 PC12, B1 PE2, B2 PE3, B3 PE0, B4 PB8, B5 PB5, B6 PG15, B7 PG9, B8 PD5, B9 PD2, B10 PC10, B11 PA14, B12 PA10, C1 PC14-OSC32_IN, C3 PE4, C4 PE5, C5 PB7, C6 PG13, C7 PD4, C8 PC11, C9 PA15, C10 PA13, C11 PA12, C12 PA11, D2 PC15-OSC32_OUT, D3 PE6, D6 PB3, D7 PD6, D8 PD0, D11 PA8, D12 PC8, E1 DSI_D0N, E2 DSI_D0P, E4 PC13, E5 PF0, E7 PD1, E9 PA9, E11 PI2, E12 PI3, F1 DSI_CKN, F2 DSI_CKP, F4 PF1, F8 PC9, F9 PC7, F11 PI0, F12 PI1, G1 DSI_D1N, G2 DSI_D1P, G4 PF2, G5 PC2, G9 PC6, G11 PH14, G12 PH15, H2 PH0-OSC_IN, H4 PA0, H6 PB2, H8 PE8, H9 PD15, H11 PH12, H12 PH13, J1 PH1-OSC_OUT, J2 NRST, J5 PB0, J6 PG1, J7 PE10, J8 PE12, J11 PH11, J12 PH10, K1 PC1, K2 PC0, K3 PA1, K4 PA5, K5 PG0, K6 PE9, K7 PE14, K8 PB10, K9 PD13, K10 PD9, K11 PD12, K12 PH9, L1 PC3, L2 PA2, L3 PA4, L4 PA7, L5 PE7, L6 PE13, L7 PB11, L9 PD11, L10 PB14, L11 PD10, L12 PD14, M2 PA3, M3 PA6, M4 PB1, M5 PE11, M6 PE15, M9 PB15, M10 PB13, M11 PD8
part B pins: A1 VSS, A12 VSS, C2 VBAT, D1 VSSDSI, D4 VDD11, D5 VSS, D9 VSS, D10 VDDUSB, E3 VDDDSI, E6 VDDIO2, E8 VDD, E10 VDD, F3 VSSDSI, F5 VDD, F6 VSS, F7 VSS, F10 VSS, G3 VDD11DSI, G6 VSS, G7 VSS, G8 VDD, G10 VDD, H1 VSSDSI, H3 VREF+/VREFBUF_OUT, H5 VDD, H7 VDD, H10 VSS, J3 VSSA, J4 VDDA, J9 VDD11, J10 VDD, L8 VSSSMPS, M1 VSS, M7 VLXSMPS, M8 VDDSMPS, M12 VSS

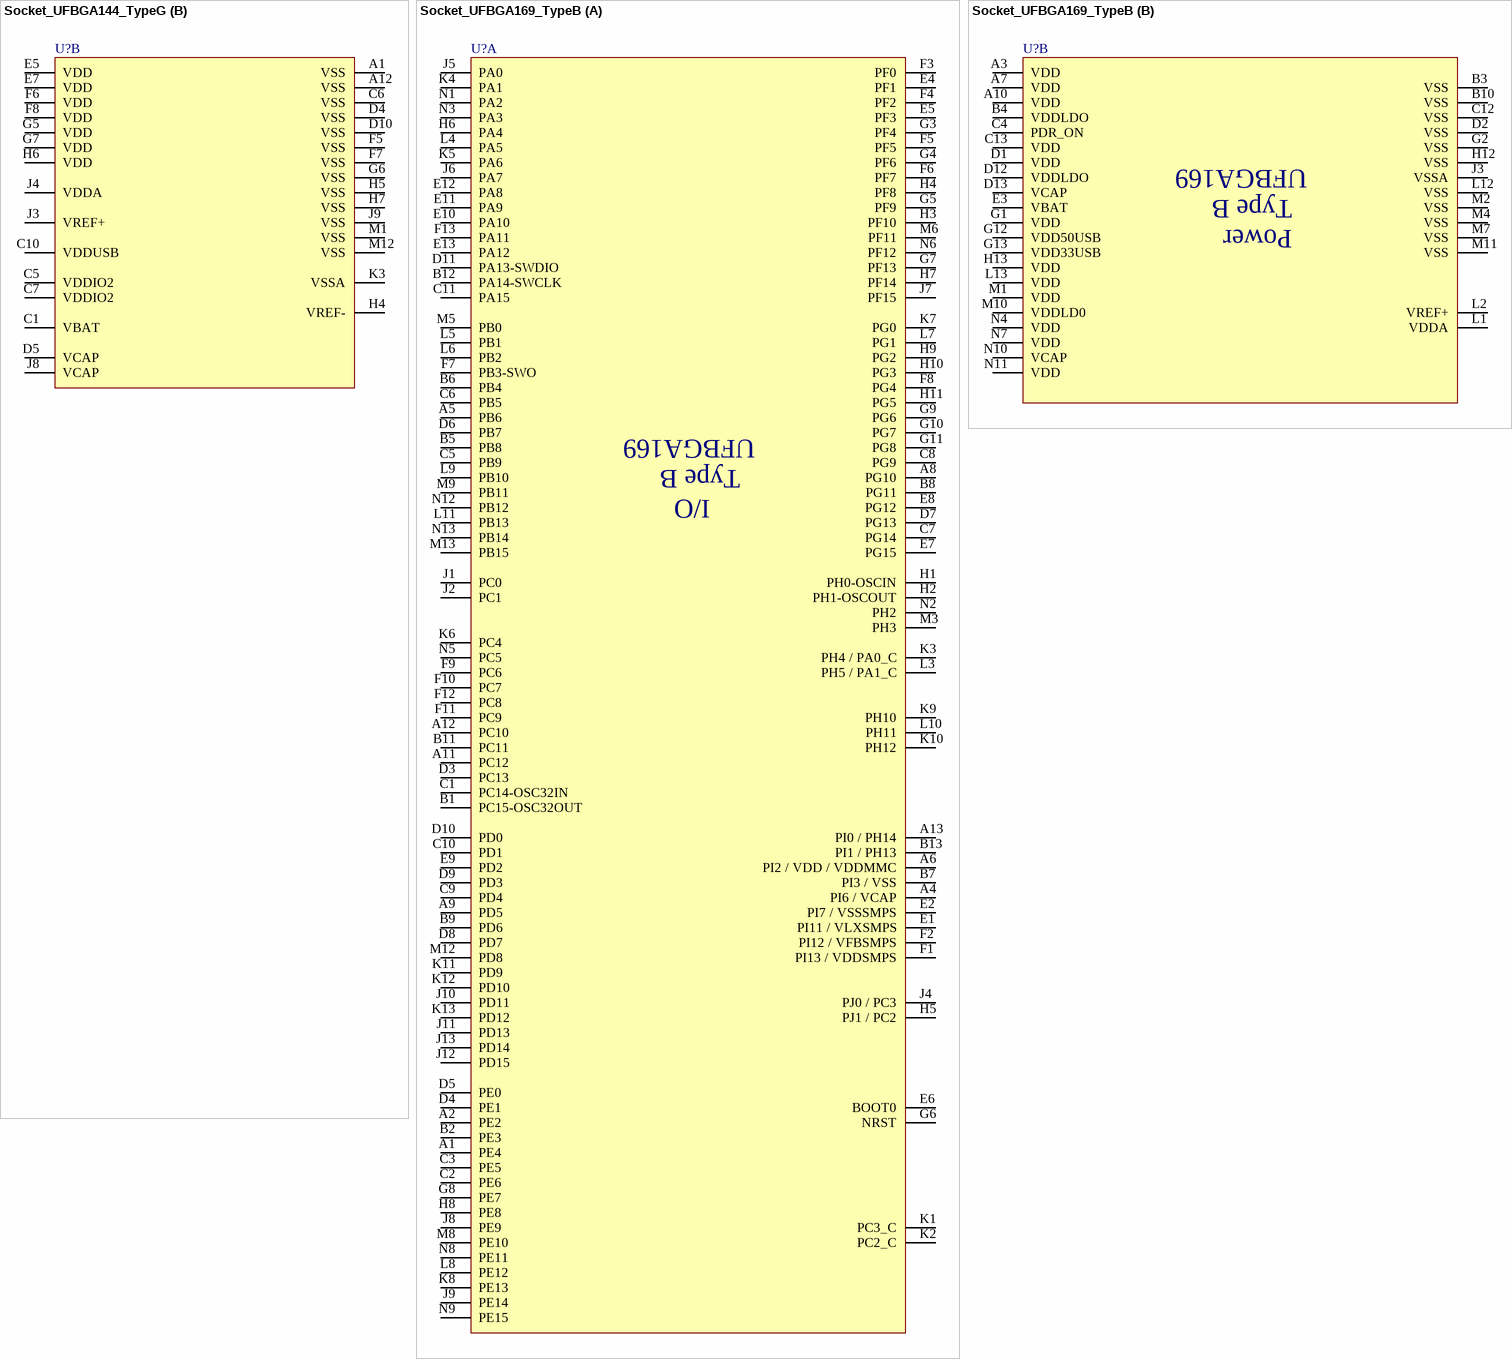
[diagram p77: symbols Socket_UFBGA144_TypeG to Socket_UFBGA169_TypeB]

## Socket_UFBGA144_TypeG
designator U?
part A pins: A2 PB9, A3 PB7, A4 PB4, A5 PG15, A6 PG12, A7 PG11, A8 PD7, A9 PD4, A10 PD2, A11 PC10, B1 PE2, B2 PE0, B3 PB8, B4 PB6, B5 PB3, B6 PG14, B7 PG10, B8 PD6, B9 PD3, B10 PC12, B11 PA14, B12 PA10, C2 PE4, C3 PE3, C4 BOOT0, C8 PD5, C9 PD1, C11 PA12, C12 PA11, D1 PC15-OSC32_OUT, D2 PC14-OSC32_IN, D3 PE5, D6 PG13, D7 PG9, D8 PD0, D9 PC11, D11 PA9, D12 PA8, E1 PF1, E2 PF0, E3 PC13, E4 PE6, E6 PB5, E8 PA15, E9 PA13, E10 PC9, E11 PC8, E12 PC7, F1 PF5, F2 PF4, F3 PF3, F4 PF2, F9 PC6, F10 PG8, F11 PG7, F12 PG6, G1 PF6, G2 PF7, G3 PF9, G4 PF8, G8 PD11, G9 PD15, G10 PG3, G11 PG4, G12 PG5, H1 PH0-OSC_IN, H2 PH1-OSC_OUT, H3 PF10, H8 PB14, H9 PB15, H10 PD12, H11 PD14, H12 PG2, J1 NRST, J2 PC0, J5 PA7, J6 PB1, J7 PG1, J10 PD8, J11 PD9, J12 PD13, K1 PC2, K2 PC1, K4 PA2, K5 PC4, K6 PB2, K7 PF15, K8 PE9, K9 PE12, K10 PE15, K11 PB13, K12 PD10, L1 PC3, L2 PA0, L3 PA1, L4 PA5, L5 PC5, L6 PF11, L7 PF14, L8 PE7, L9 PE10, L10 PE14, L11 PB10, L12 PB12, M2 PA3, M3 PA4, M4 PA6, M5 PB0, M6 PF12, M7 PF13, M8 PG0, M9 PE8, M10 PE11, M11 PE13
part B pins: A1 VSS, A12 VSS, C1 VBAT, C5 VDDIO2, C6 VSS, C7 VDDIO2, C10 VDDUSB, D4 VSS, D5 VCAP, D10 VSS, E5 VDD, E7 VDD, F5 VSS, F6 VDD, F7 VSS, F8 VDD, G5 VDD, G6 VSS, G7 VDD, H4 VREF-, H5 VSS, H6 VDD, H7 VSS, J3 VREF+, J4 VDDA, J8 VCAP, J9 VSS, K3 VSSA, M1 VSS, M12 VSS

## Socket_UFBGA169_TypeB
designator U?
part A pins: A1 PE4, A2 PE2, A4 PI6 / VCAP, A5 PB6, A6 PI2 / VDD / VDDMMC, A8 PG10, A9 PD5, A11 PC12, A12 PC10, A13 PI0 / PH14, B1 PC15-OSC32OUT, B2 PE3, B5 PB8, B6 PB4, B7 PI3 / VSS, B8 PG11, B9 PD6, B11 PC11, B12 PA14-SWCLK, B13 PI1 / PH13, C1 PC14-OSC32IN, C2 PE6, C3 PE5, C5 PB9, C6 PB5, C7 PG14, C8 PG9, C9 PD4, C10 PD1, C11 PA15, D3 PC13, D4 PE1, D5 PE0, D6 PB7, D7 PG13, D8 PD7, D9 PD3, D10 PD0, D11 PA13-SWDIO, E1 PI11 / VLXSMPS, E2 PI7 / VSSSMPS, E4 PF1, E5 PF3, E6 BOOT0, E7 PG15, E8 PG12, E9 PD2, E10 PA10, E11 PA9, E12 PA8, E13 PA12, F1 PI13 / VDDSMPS, F2 PI12 / VFBSMPS, F3 PF0, F4 PF2, F5 PF5, F6 PF7, F7 PB3-SWO, F8 PG4, F9 PC6, F10 PC7, F11 PC9, F12 PC8, F13 PA11, G3 PF4, G4 PF6, G5 PF9, G6 NRST, G7 PF13, G8 PE7, G9 PG6, G10 PG7, G11 PG8, H1 PH0-OSCIN, H2 PH1-OSCOUT, H3 PF10, H4 PF8, H5 PJ1 / PC2, H6 PA4, H7 PF14, H8 PE8, H9 PG2, H10 PG3, H11 PG5, J1 PC0, J2 PC1, J4 PJ0 / PC3, J5 PA0, J6 PA7, J7 PF15, J8 PE9, J9 PE14, J10 PD11, J11 PD13, J12 PD15, J13 PD14, K1 PC3_C, K2 PC2_C, K3 PH4 / PA0_C, K4 PA1, K5 PA6, K6 PC4, K7 PG0, K8 PE13, K9 PH10, K10 PH12, K11 PD9, K12 PD10, K13 PD12, L3 PH5 / PA1_C, L4 PA5, L5 PB1, L6 PB2, L7 PG1, L8 PE12, L9 PB10, L10 PH11, L11 PB13, M3 PH3, M5 PB0, M6 PF11, M8 PE10, M9 PB11, M12 PD8, M13 PB15, N1 PA2, N2 PH2, N3 PA3, N5 PC5, N6 PF12, N8 PE11, N9 PE15, N12 PB12, N13 PB14
part B pins: A3 VDD, A7 VDD, A10 VDD, B3 VSS, B4 VDDLDO, B10 VSS, C4 PDR_ON, C12 VSS, C13 VDD, D1 VDD, D2 VSS, D12 VDDLDO, D13 VCAP, E3 VBAT, G1 VDD, G2 VSS, G12 VDD50USB, G13 VDD33USB, H12 VSS, H13 VDD, J3 VSSA, L1 VDDA, L2 VREF+, L12 VSS, L13 VDD, M1 VDD, M2 VSS, M4 VSS, M7 VSS, M10 VDDLD0, M11 VSS, N4 VDD, N7 VDD, N10 VCAP, N11 VDD

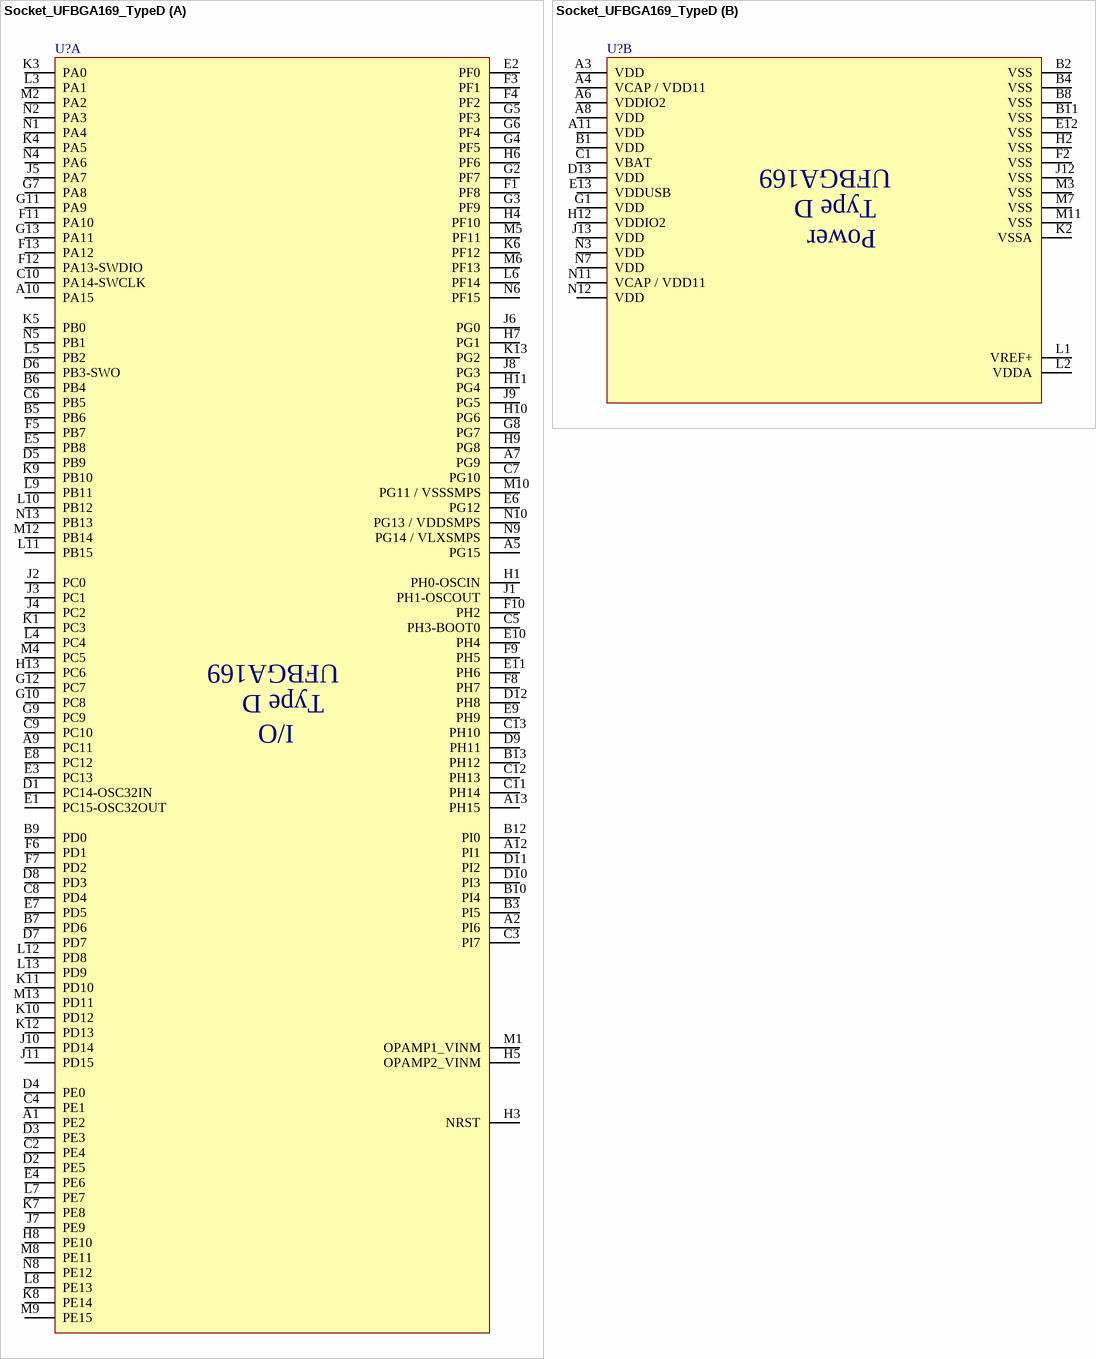
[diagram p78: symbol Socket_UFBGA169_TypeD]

## Socket_UFBGA169_TypeD
designator U?
part A pins: A1 PE2, A2 PI6, A5 PG15, A7 PG9, A9 PC11, A10 PA15, A12 PI1, A13 PH15, B3 PI5, B5 PB6, B6 PB4, B7 PD6, B9 PD0, B10 PI4, B12 PI0, B13 PH12, C2 PE4, C3 PI7, C4 PE1, C5 PH3-BOOT0, C6 PB5, C7 PG10, C8 PD4, C9 PC10, C10 PA14-SWCLK, C11 PH14, C12 PH13, C13 PH10, D1 PC14-OSC32IN, D2 PE5, D3 PE3, D4 PE0, D5 PB9, D6 PB3-SWO, D7 PD7, D8 PD3, D9 PH11, D10 PI3, D11 PI2, D12 PH8, E1 PC15-OSC32OUT, E2 PF0, E3 PC13, E4 PE6, E5 PB8, E6 PG12, E7 PD5, E8 PC12, E9 PH9, E10 PH4, E11 PH6, F1 PF8, F3 PF1, F4 PF2, F5 PB7, F6 PD1, F7 PD2, F8 PH7, F9 PH5, F10 PH2, F11 PA10, F12 PA13-SWDIO, F13 PA12, G2 PF7, G3 PF9, G4 PF5, G5 PF3, G6 PF4, G7 PA8, G8 PG7, G9 PC9, G10 PC8, G11 PA9, G12 PC7, G13 PA11, H1 PH0-OSCIN, H3 NRST, H4 PF10, H5 OPAMP2_VINM, H6 PF6, H7 PG1, H8 PE10, H9 PG8, H10 PG6, H11 PG4, H13 PC6, J1 PH1-OSCOUT, J2 PC0, J3 PC1, J4 PC2, J5 PA7, J6 PG0, J7 PE9, J8 PG3, J9 PG5, J10 PD14, J11 PD15, K1 PC3, K3 PA0, K4 PA5, K5 PB0, K6 PF12, K7 PE8, K8 PE14, K9 PB10, K10 PD12, K11 PD10, K12 PD13, K13 PG2, L3 PA1, L4 PC4, L5 PB2, L6 PF14, L7 PE7, L8 PE13, L9 PB11, L10 PB12, L11 PB15, L12 PD8, L13 PD9, M1 OPAMP1_VINM, M2 PA2, M4 PC5, M5 PF11, M6 PF13, M8 PE11, M9 PE15, M10 PG11 / VSSSMPS, M12 PB14, M13 PD11, N1 PA4, N2 PA3, N4 PA6, N5 PB1, N6 PF15, N8 PE12, N9 PG14 / VLXSMPS, N10 PG13 / VDDSMPS, N13 PB13
part B pins: A3 VDD, A4 VCAP / VDD11, A6 VDDIO2, A8 VDD, A11 VDD, B1 VDD, B2 VSS, B4 VSS, B8 VSS, B11 VSS, C1 VBAT, D13 VDD, E12 VSS, E13 VDDUSB, F2 VSS, G1 VDD, H2 VSS, H12 VDDIO2, J12 VSS, J13 VDD, K2 VSSA, L1 VREF+, L2 VDDA, M3 VSS, M7 VSS, M11 VSS, N3 VDD, N7 VDD, N11 VCAP / VDD11, N12 VDD

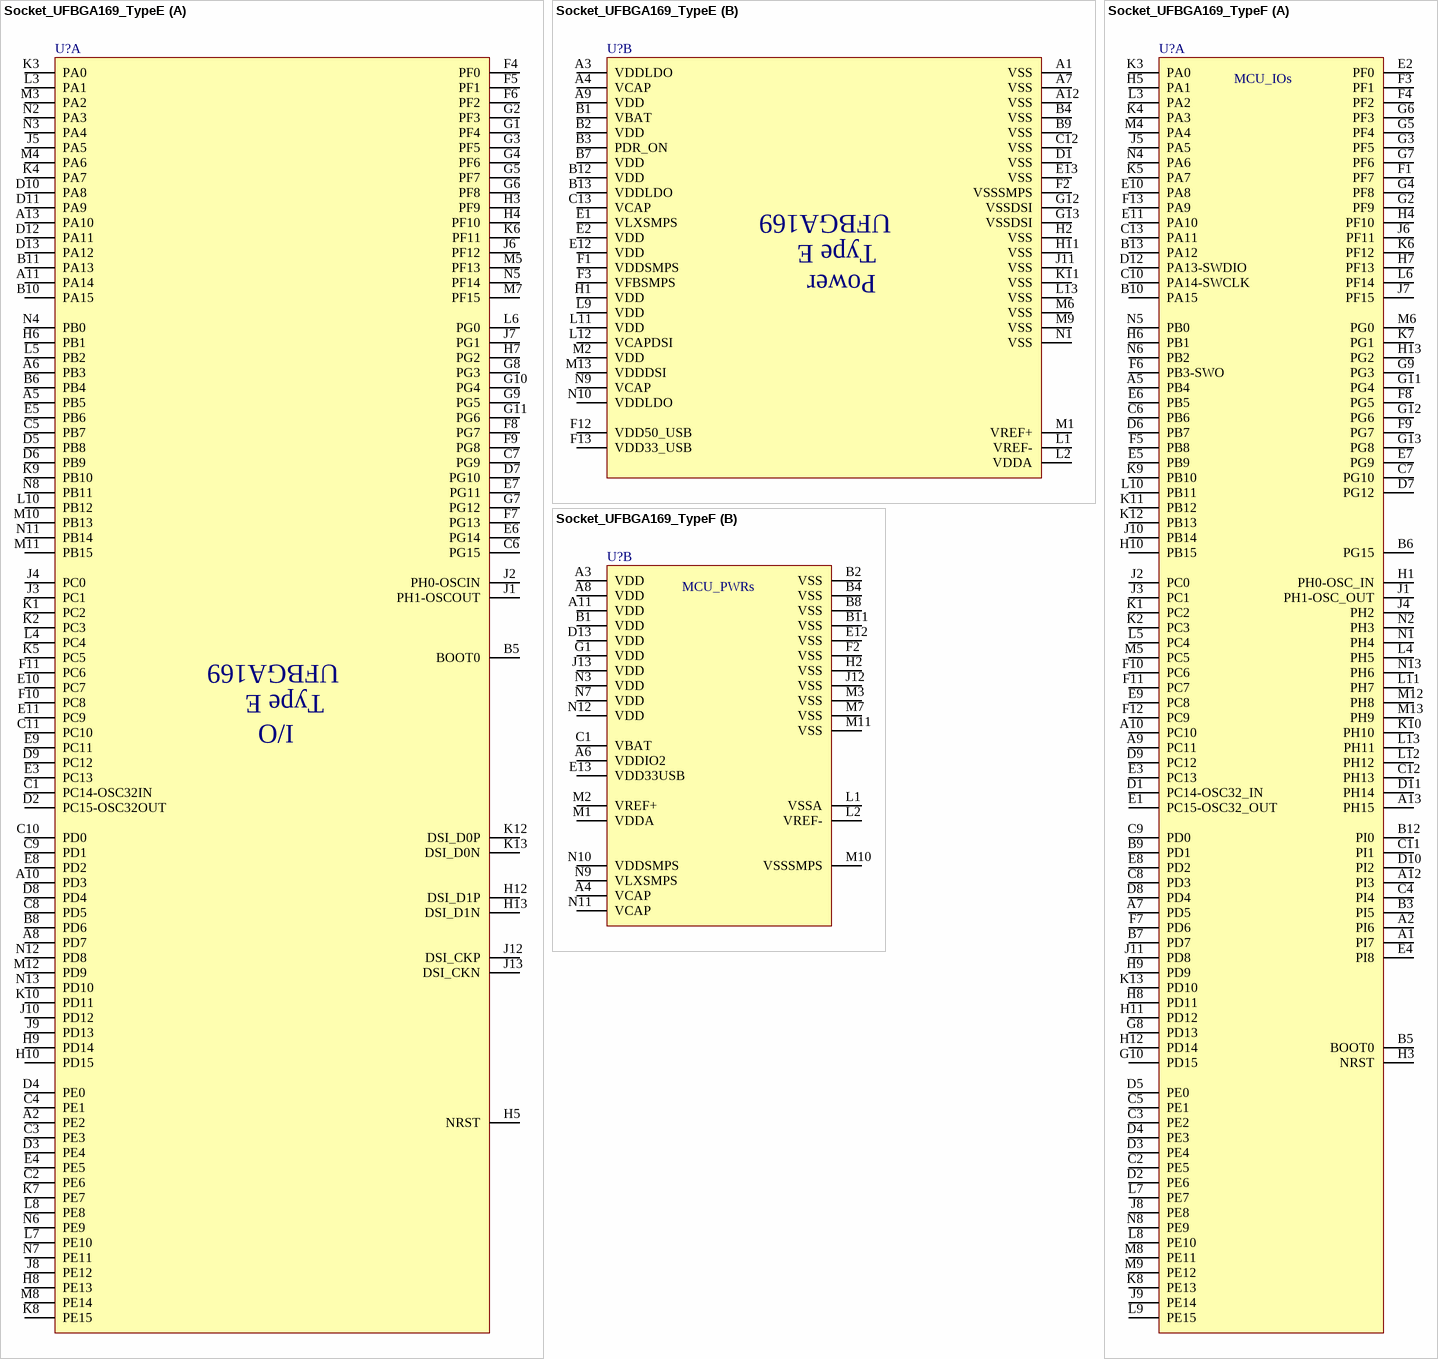
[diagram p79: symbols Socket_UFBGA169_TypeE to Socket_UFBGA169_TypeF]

## Socket_UFBGA169_TypeE
designator U?
part A pins: A2 PE2, A5 PB5, A6 PB3, A8 PD7, A10 PD3, A11 PA14, A13 PA10, B5 BOOT0, B6 PB4, B8 PD6, B10 PA15, B11 PA13, C1 PC14-OSC32IN, C2 PE6, C3 PE3, C4 PE1, C5 PB7, C6 PG15, C7 PG9, C8 PD5, C9 PD1, C10 PD0, C11 PC10, D2 PC15-OSC32OUT, D3 PE4, D4 PE0, D5 PB8, D6 PB9, D7 PG10, D8 PD4, D9 PC12, D10 PA8, D11 PA9, D12 PA11, D13 PA12, E3 PC13, E4 PE5, E5 PB6, E6 PG14, E7 PG11, E8 PD2, E9 PC11, E10 PC7, E11 PC9, F4 PF0, F5 PF1, F6 PF2, F7 PG13, F8 PG7, F9 PG8, F10 PC8, F11 PC6, G1 PF4, G2 PF3, G3 PF5, G4 PF6, G5 PF7, G6 PF8, G7 PG12, G8 PG3, G9 PG5, G10 PG4, G11 PG6, H3 PF9, H4 PF10, H5 NRST, H6 PB1, H7 PG2, H8 PE13, H9 PD14, H10 PD15, H12 DSI_D1P, H13 DSI_D1N, J1 PH1-OSCOUT, J2 PH0-OSCIN, J3 PC1, J4 PC0, J5 PA5, J6 PF12, J7 PG1, J8 PE12, J9 PD13, J10 PD12, J12 DSI_CKP, J13 DSI_CKN, K1 PC2, K2 PC3, K3 PA0, K4 PA7, K5 PC5, K6 PF11, K7 PE7, K8 PE15, K9 PB10, K10 PD11, K12 DSI_D0P, K13 DSI_D0N, L3 PA1, L4 PC4, L5 PB2, L6 PG0, L7 PE10, L8 PE8, L10 PB12, M3 PA2, M4 PA6, M5 PF13, M7 PF15, M8 PE14, M10 PB13, M11 PB15, M12 PD9, N2 PA3, N3 PA4, N4 PB0, N5 PF14, N6 PE9, N7 PE11, N8 PB11, N11 PB14, N12 PD8, N13 PD10
part B pins: A1 VSS, A3 VDDLDO, A4 VCAP, A7 VSS, A9 VDD, A12 VSS, B1 VBAT, B2 VDD, B3 PDR_ON, B4 VSS, B7 VDD, B9 VSS, B12 VDD, B13 VDDLDO, C12 VSS, C13 VCAP, D1 VSS, E1 VLXSMPS, E2 VDD, E12 VDD, E13 VSS, F1 VDDSMPS, F2 VSSSMPS, F3 VFBSMPS, F12 VDD50_USB, F13 VDD33_USB, G12 VSSDSI, G13 VSSDSI, H1 VDD, H2 VSS, H11 VSS, J11 VSS, K11 VSS, L1 VREF-, L2 VDDA, L9 VDD, L11 VDD, L12 VCAPDSI, L13 VSS, M1 VREF+, M2 VDD, M6 VSS, M9 VSS, M13 VDDDSI, N1 VSS, N9 VCAP, N10 VDDLDO

## Socket_UFBGA169_TypeF
designator U?
part A pins: A1 PI7, A2 PI6, A5 PB4, A7 PD5, A9 PC11, A10 PC10, A12 PI3, A13 PH15, B3 PI5, B5 BOOT0, B6 PG15, B7 PD7, B9 PD1, B10 PA15, B12 PI0, B13 PA12, C2 PE5, C3 PE2, C4 PI4, C5 PE1, C6 PB6, C7 PG10, C8 PD3, C9 PD0, C10 PA14-SWCLK, C11 PI1, C12 PH13, C13 PA11, D1 PC14-OSC32_IN, D2 PE6, D3 PE4, D4 PE3, D5 PE0, D6 PB7, D7 PG12, D8 PD4, D9 PC12, D10 PI2, D11 PH14, D12 PA13-SWDIO, E1 PC15-OSC32_OUT, E2 PF0, E3 PC13, E4 PI8, E5 PB9, E6 PB5, E7 PG9, E8 PD2, E9 PC8, E10 PA8, E11 PA10, F1 PF7, F3 PF1, F4 PF2, F5 PB8, F6 PB3-SWO, F7 PD6, F8 PG5, F9 PG7, F10 PC6, F11 PC7, F12 PC9, F13 PA9, G2 PF9, G3 PF5, G4 PF8, G5 PF4, G6 PF3, G7 PF6, G8 PD13, G9 PG3, G10 PD15, G11 PG4, G12 PG6, G13 PG8, H1 PH0-OSC_IN, H3 NRST, H4 PF10, H5 PA1, H6 PB1, H7 PF13, H8 PD11, H9 PD9, H10 PB15, H11 PD12, H12 PD14, H13 PG2, J1 PH1-OSC_OUT, J2 PC0, J3 PC1, J4 PH2, J5 PA5, J6 PF11, J7 PF15, J8 PE8, J9 PE14, J10 PB14, J11 PD8, K1 PC2, K2 PC3, K3 PA0, K4 PA3, K5 PA7, K6 PF12, K7 PG1, K8 PE13, K9 PB10, K10 PH10, K11 PB12, K12 PB13, K13 PD10, L3 PA2, L4 PH5, L5 PC4, L6 PF14, L7 PE7, L8 PE10, L9 PE15, L10 PB11, L11 PH7, L12 PH12, L13 PH11, M4 PA4, M5 PC5, M6 PG0, M8 PE11, M9 PE12, M12 PH8, M13 PH9, N1 PH4, N2 PH3, N4 PA6, N5 PB0, N6 PB2, N8 PE9, N13 PH6
part B pins: A3 VDD, A4 VCAP, A6 VDDIO2, A8 VDD, A11 VDD, B1 VDD, B2 VSS, B4 VSS, B8 VSS, B11 VSS, C1 VBAT, D13 VDD, E12 VSS, E13 VDD33USB, F2 VSS, G1 VDD, H2 VSS, J12 VSS, J13 VDD, L1 VSSA, L2 VREF-, M1 VDDA, M2 VREF+, M3 VSS, M7 VSS, M10 VSSSMPS, M11 VSS, N3 VDD, N7 VDD, N9 VLXSMPS, N10 VDDSMPS, N11 VCAP, N12 VDD

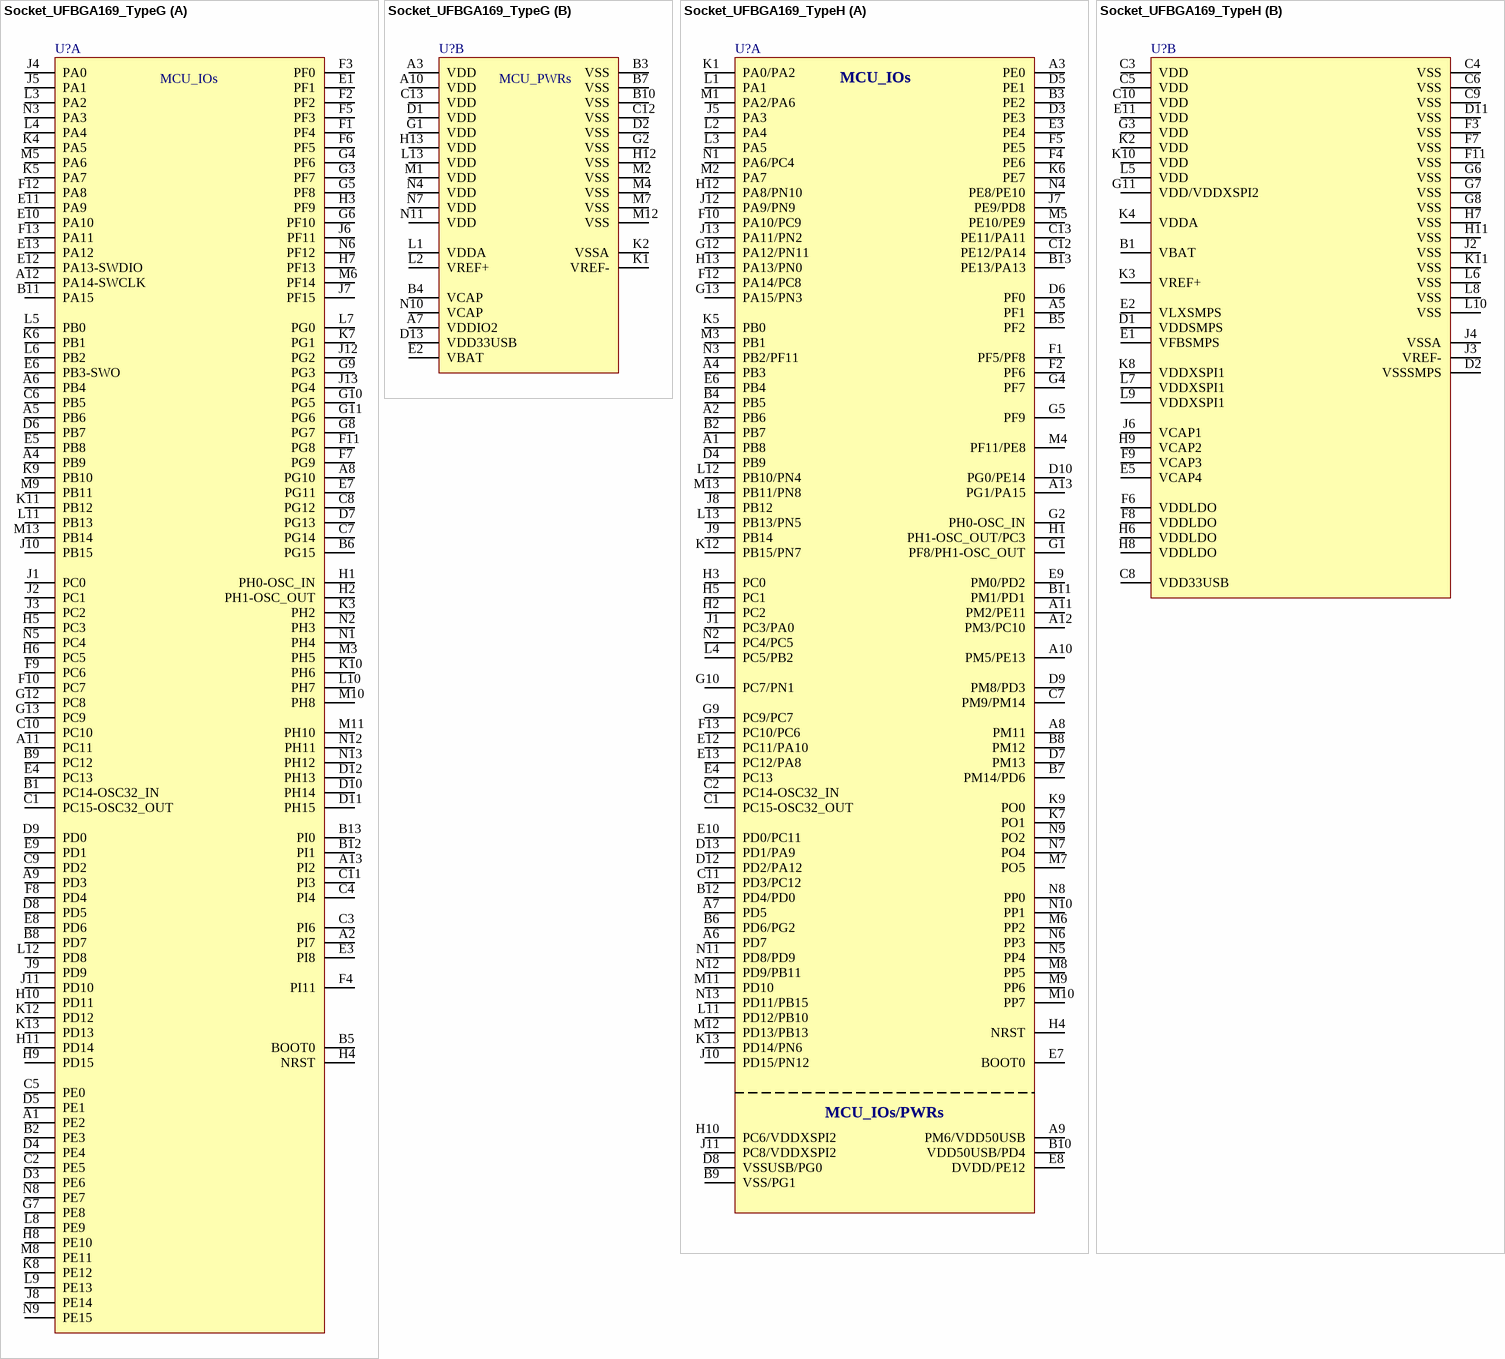
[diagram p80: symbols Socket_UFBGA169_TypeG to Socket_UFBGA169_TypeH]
